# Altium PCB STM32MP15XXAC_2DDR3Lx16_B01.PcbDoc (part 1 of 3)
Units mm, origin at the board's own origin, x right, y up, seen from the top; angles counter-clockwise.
Board outline 89 x 120 mm, 4 copper layers (Top Layer, Signal Layer 1, Signal Layer 2, Bottom Layer), stack 1.571 mm thick; 152 components, 117 nets, 1047 pads, 460 vias.
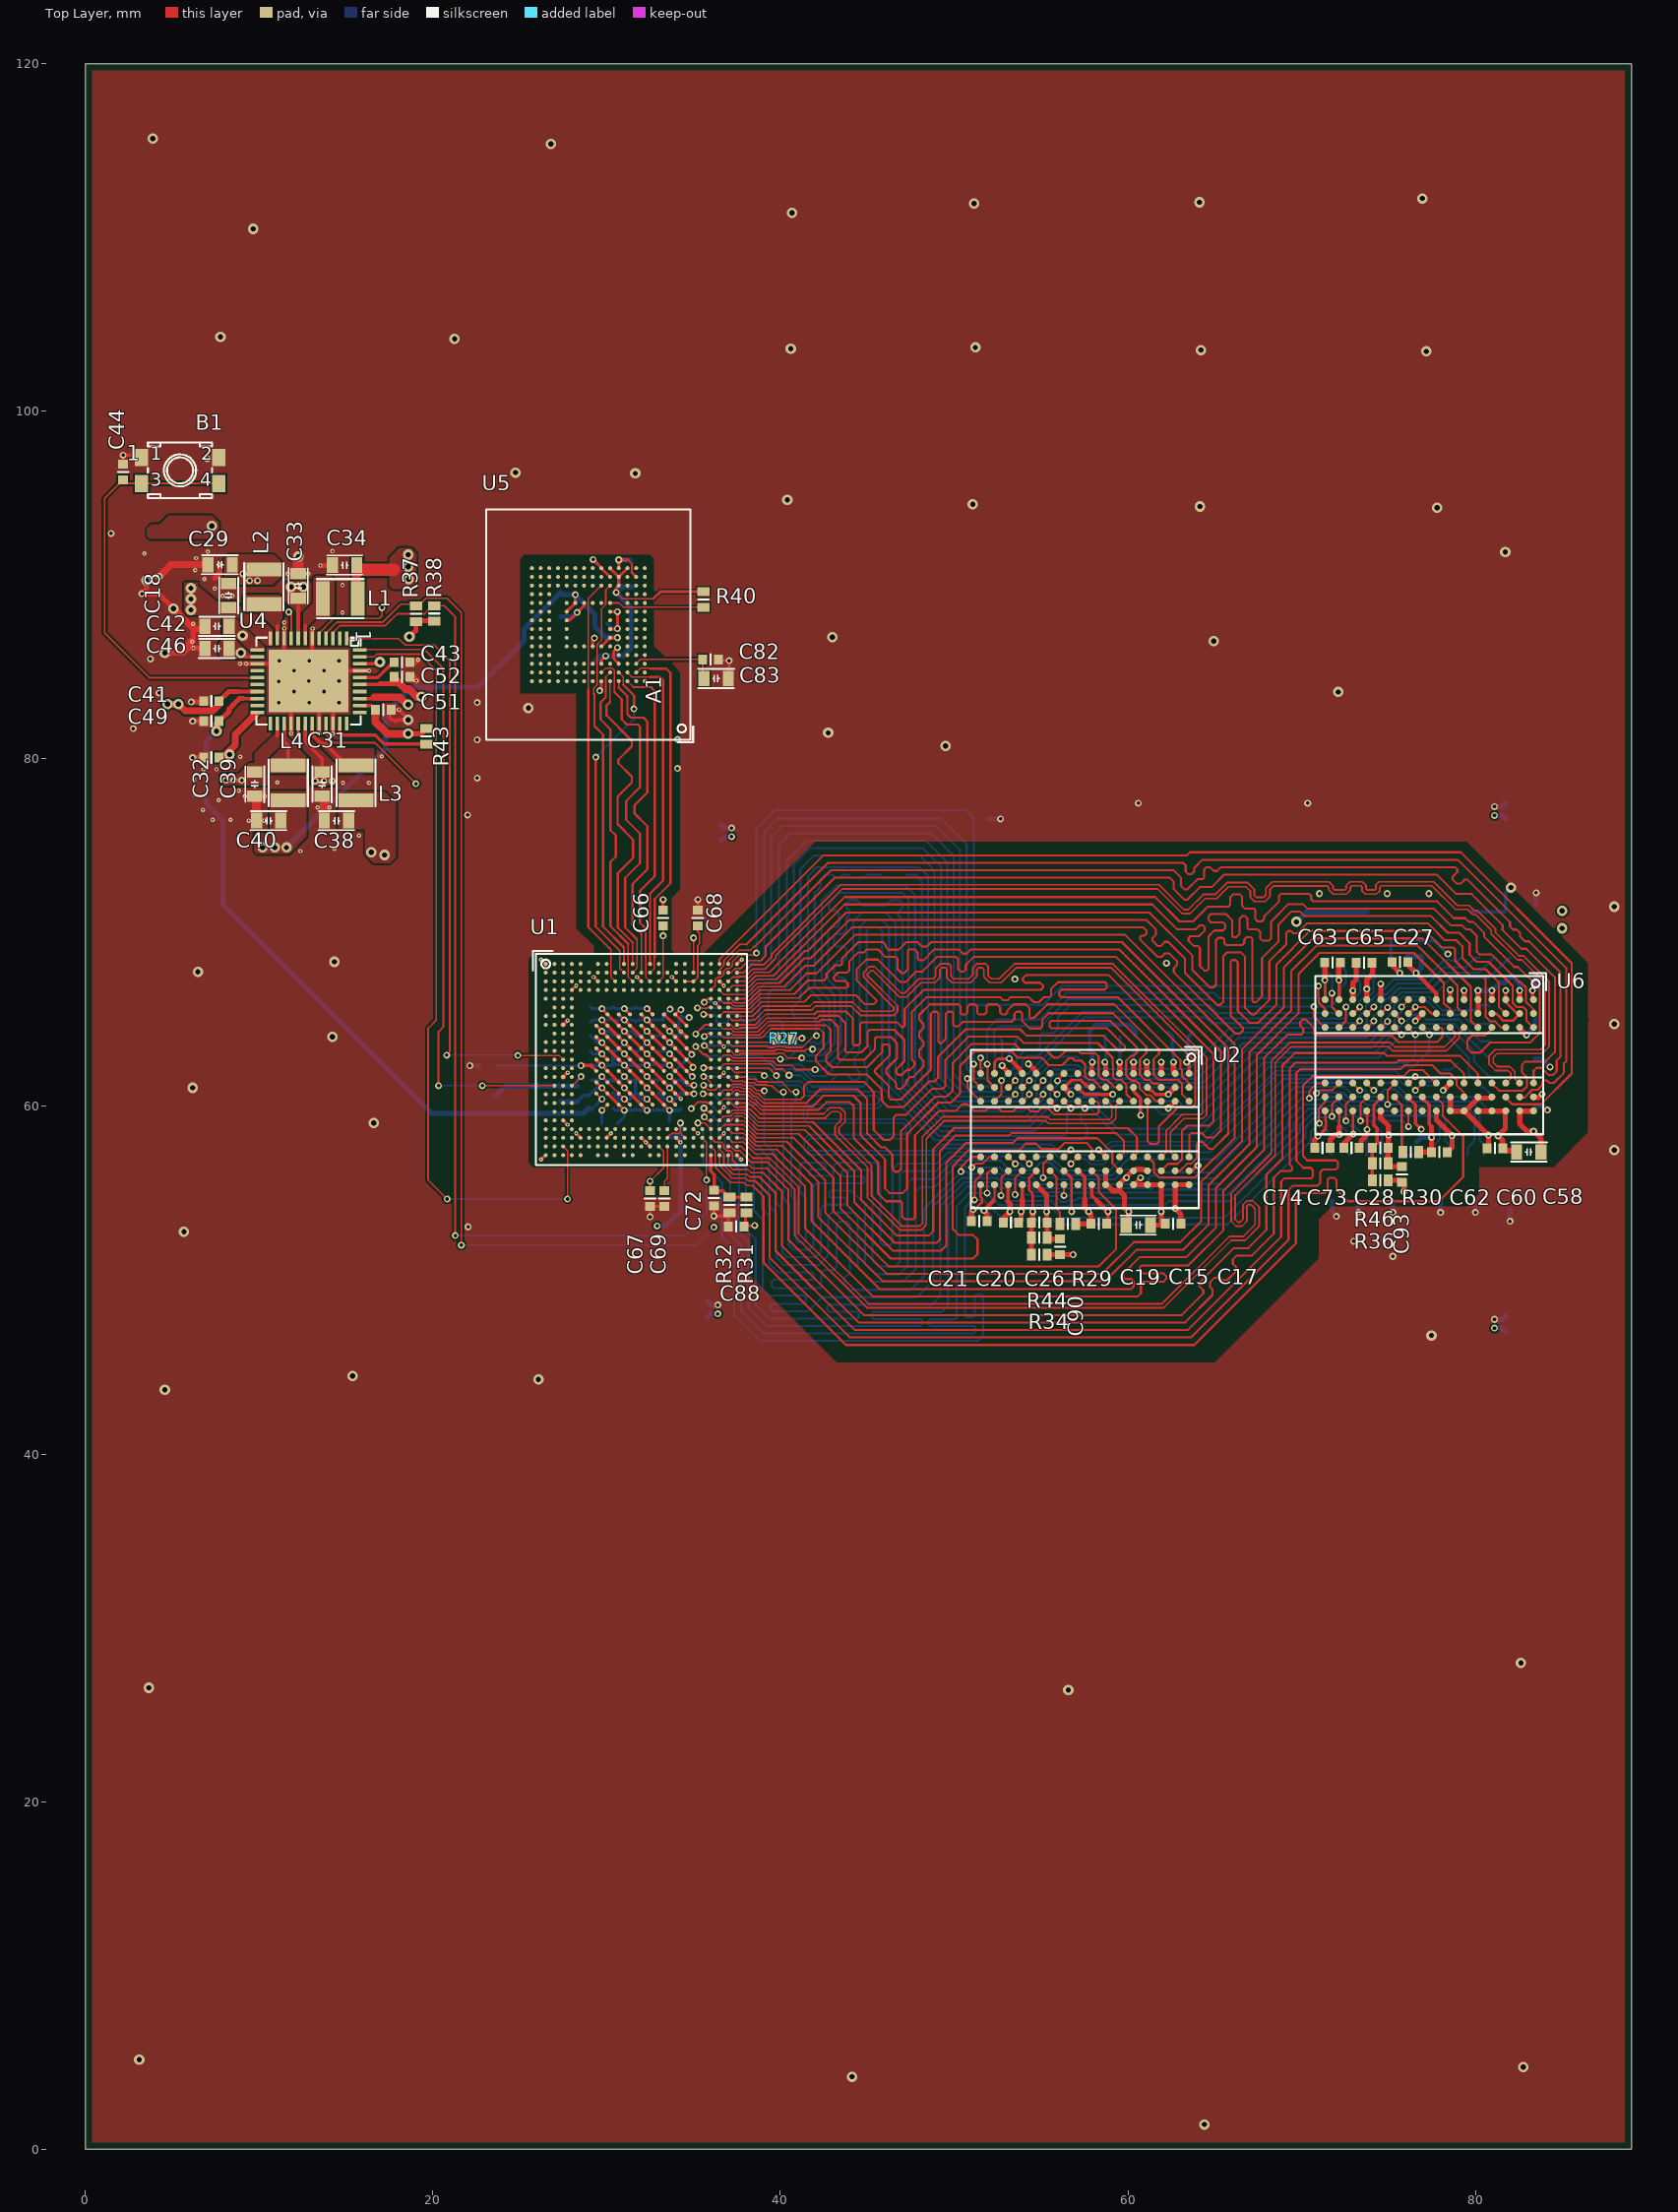
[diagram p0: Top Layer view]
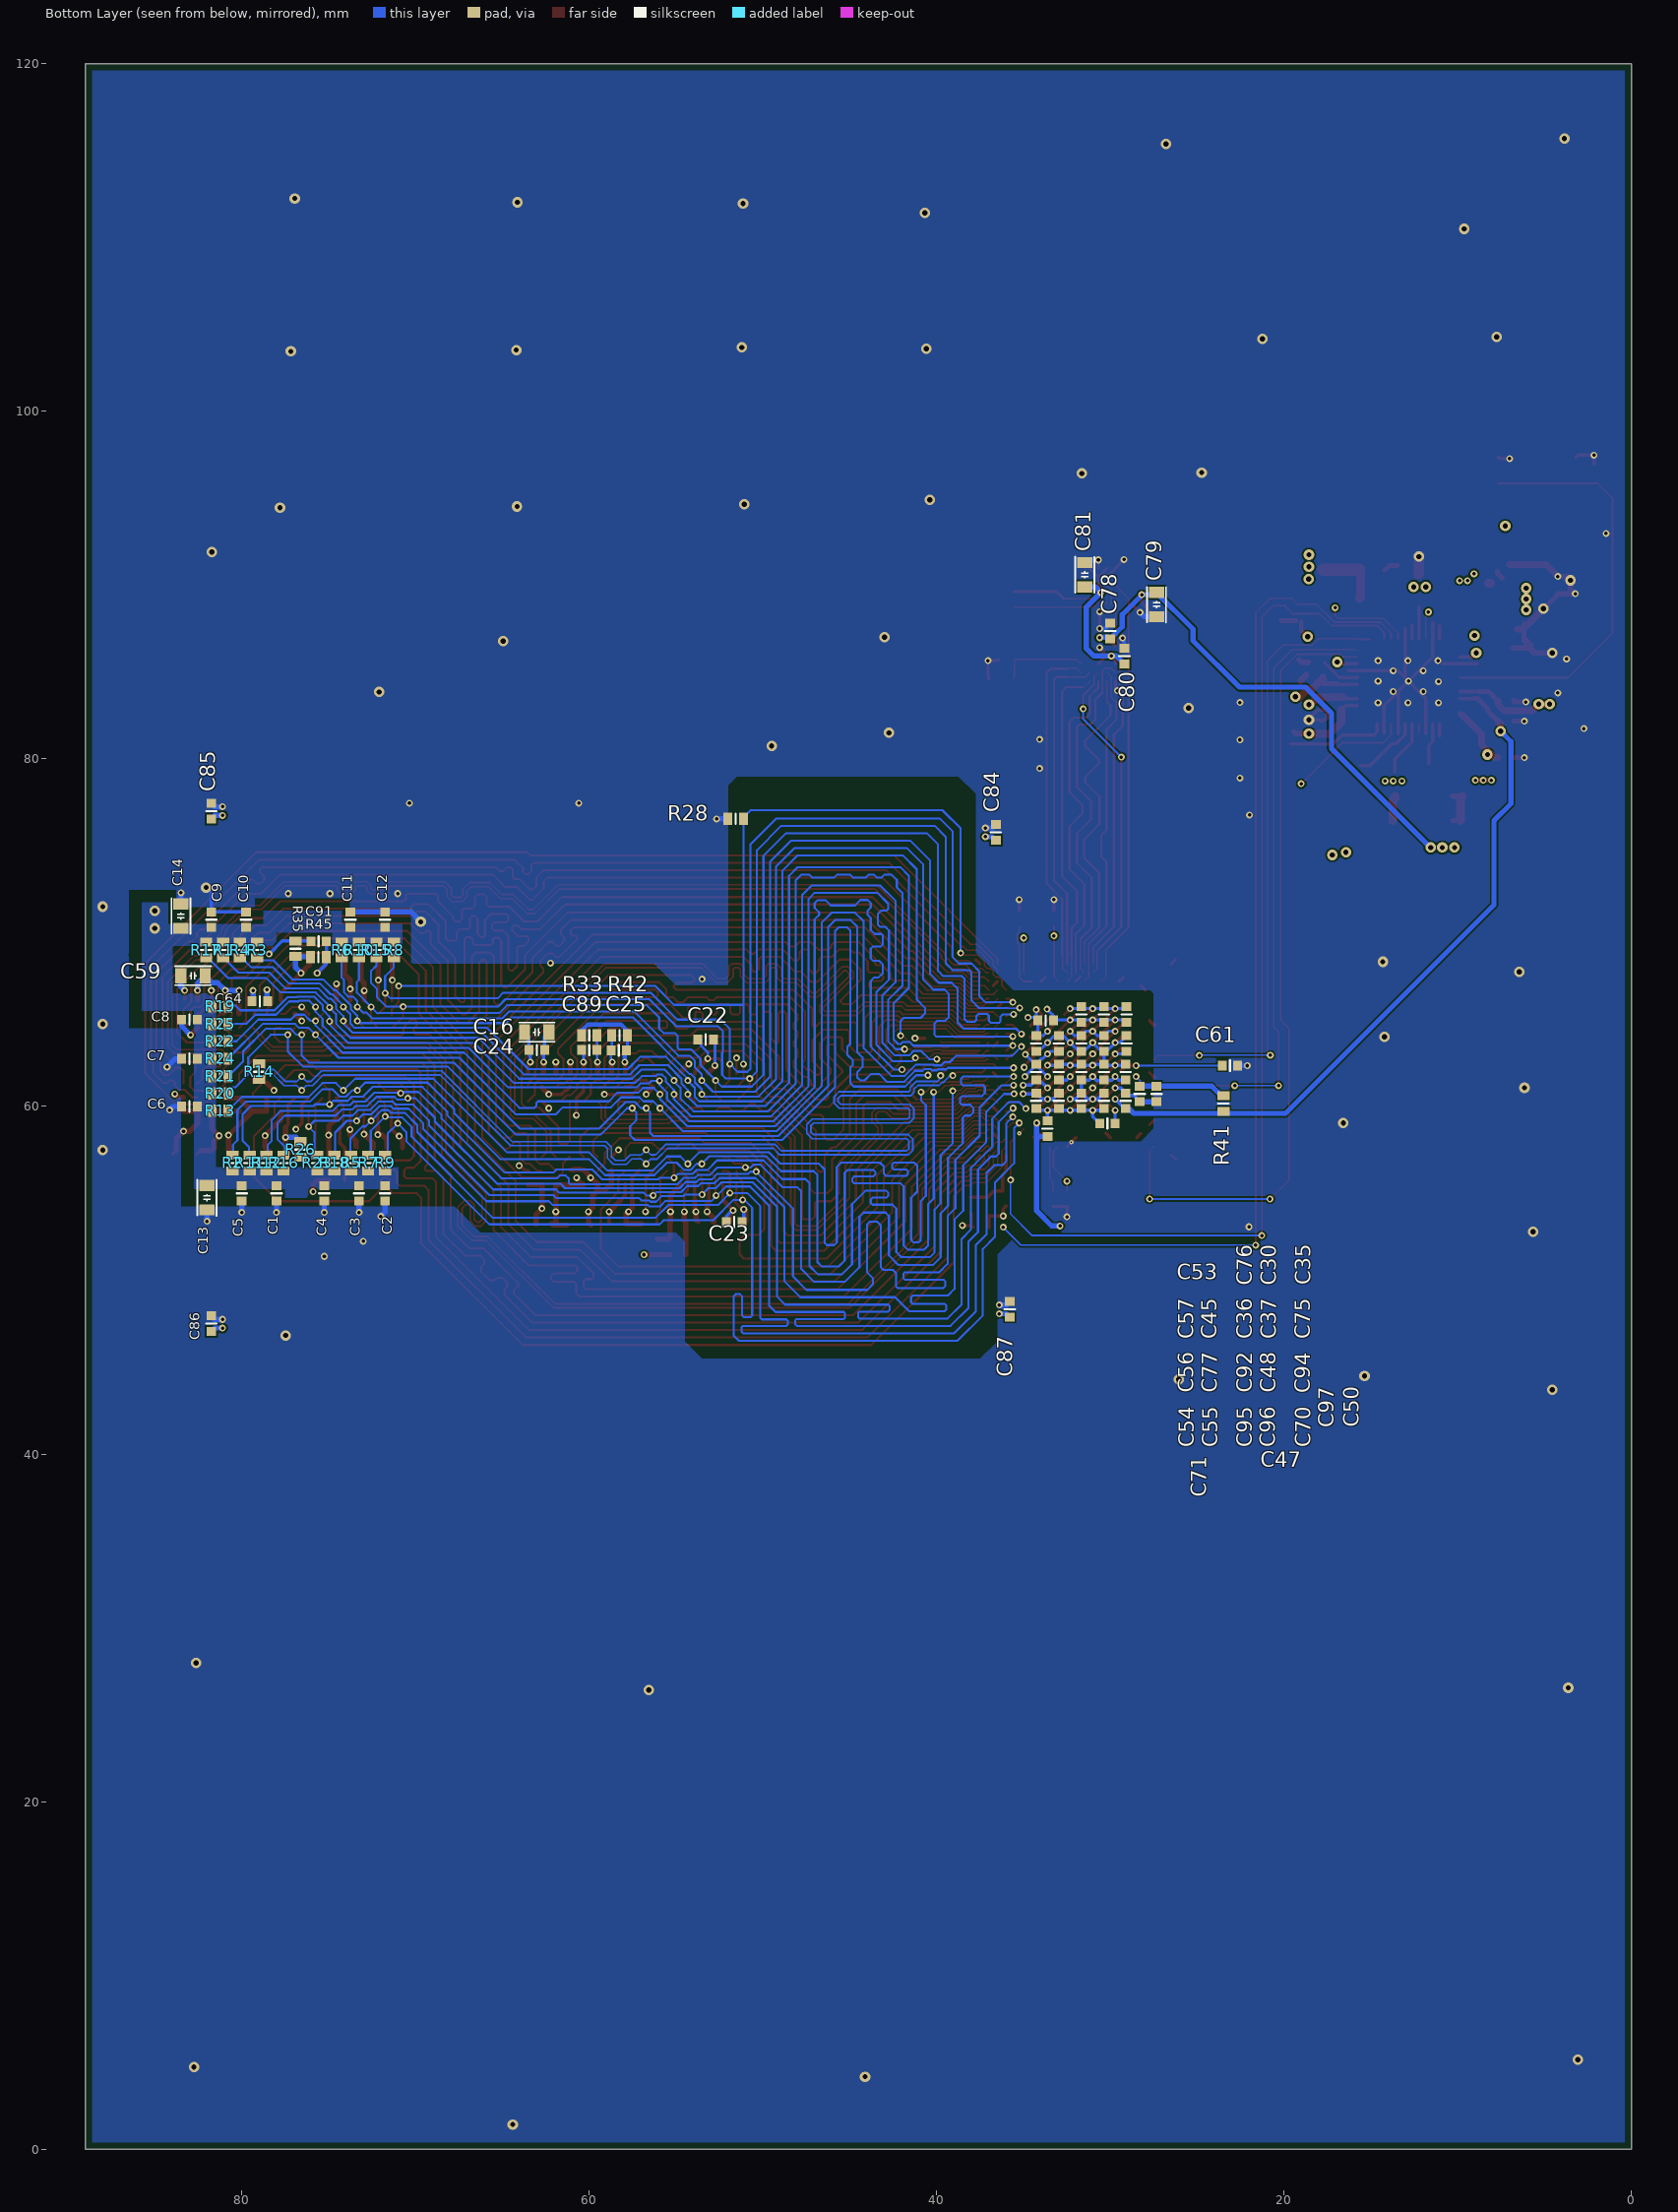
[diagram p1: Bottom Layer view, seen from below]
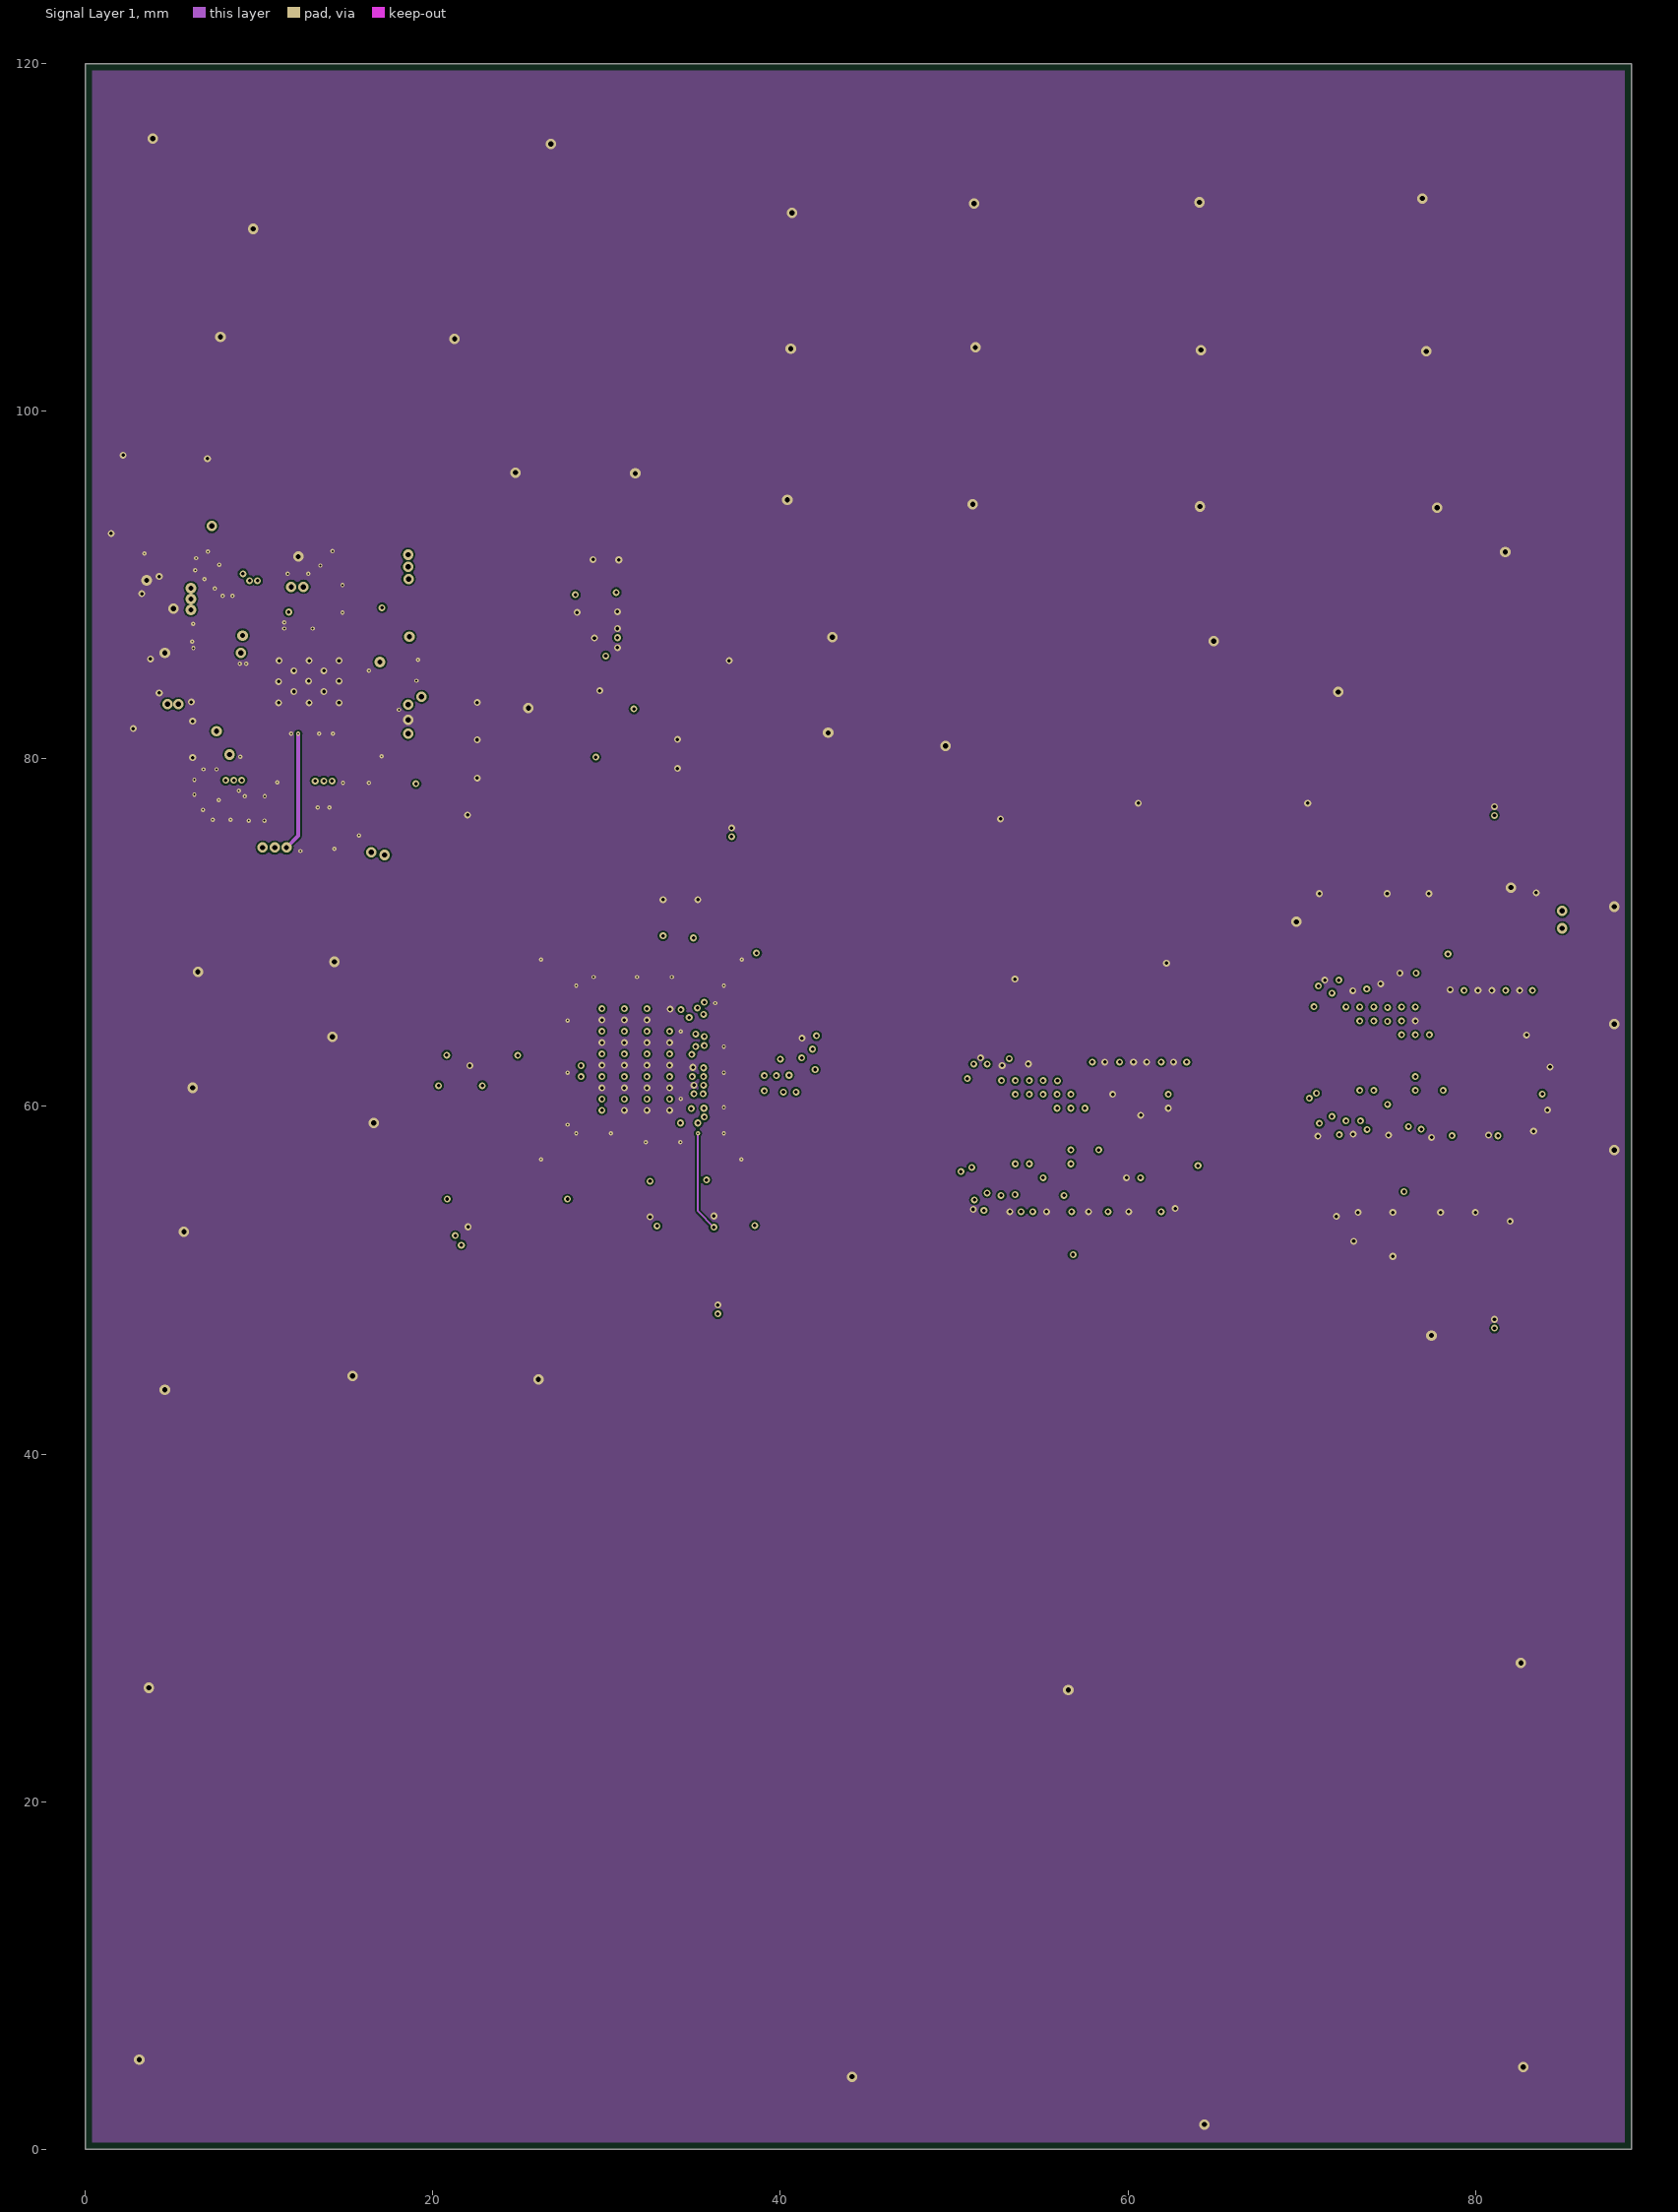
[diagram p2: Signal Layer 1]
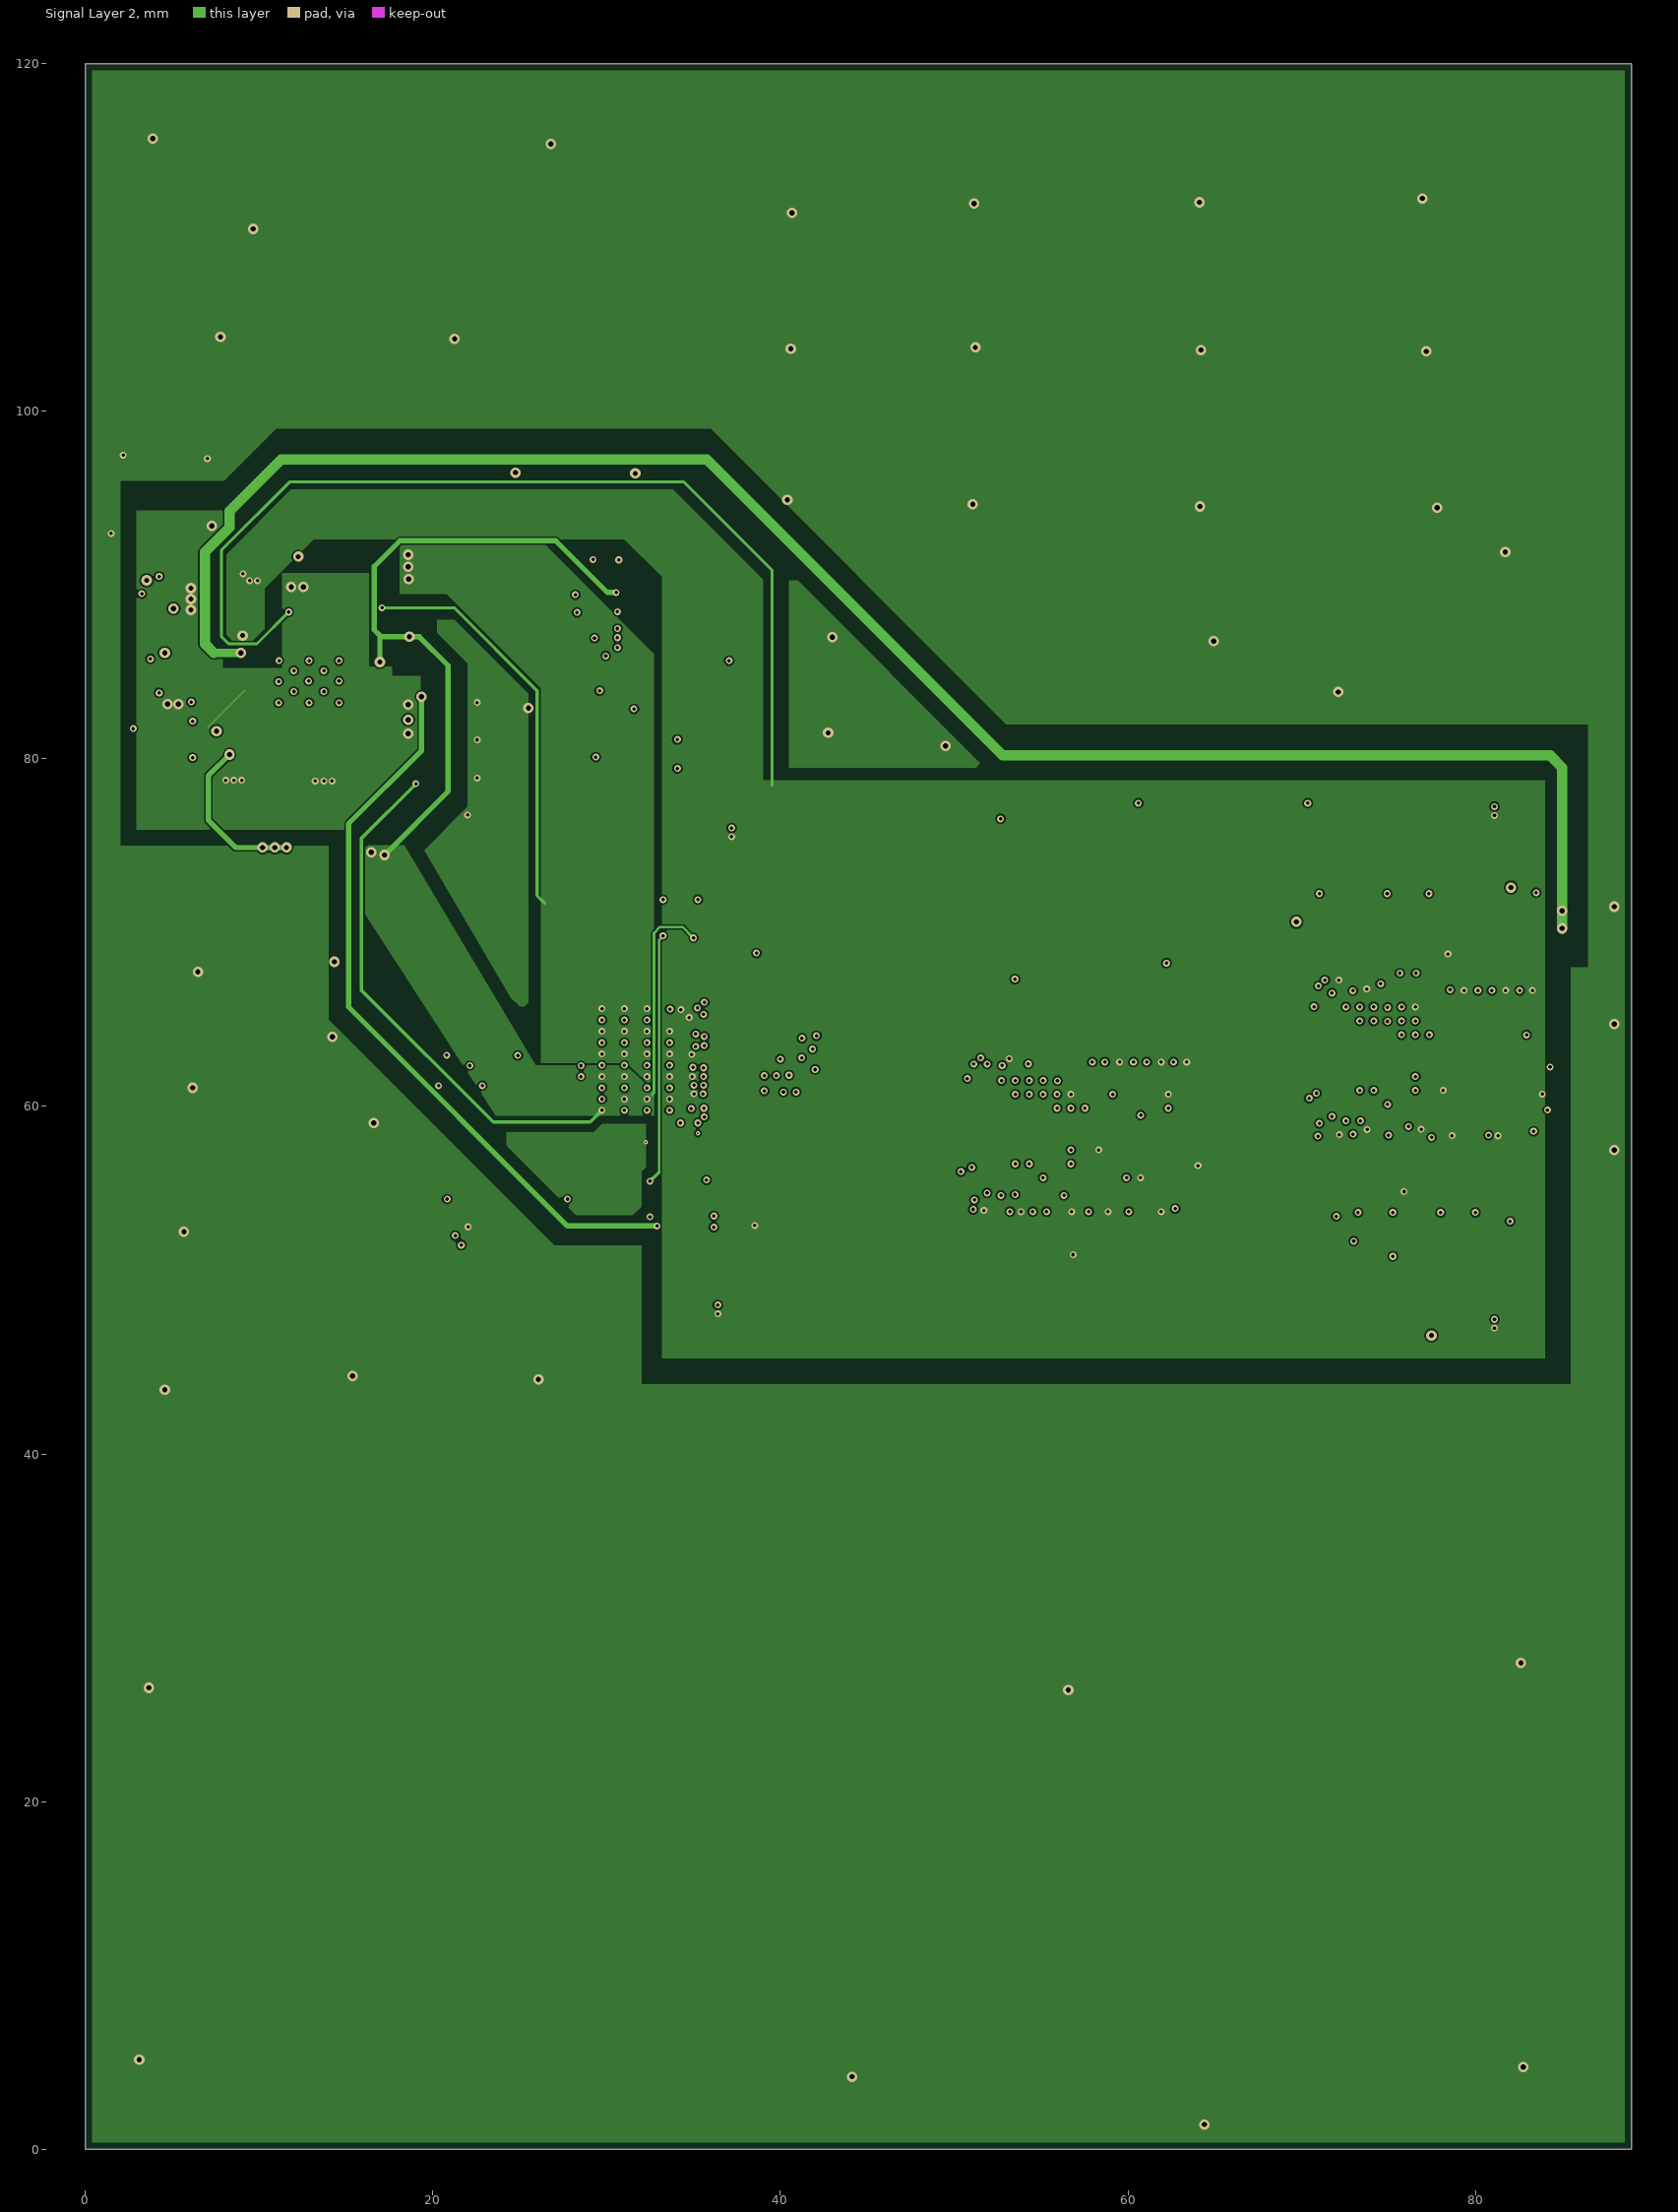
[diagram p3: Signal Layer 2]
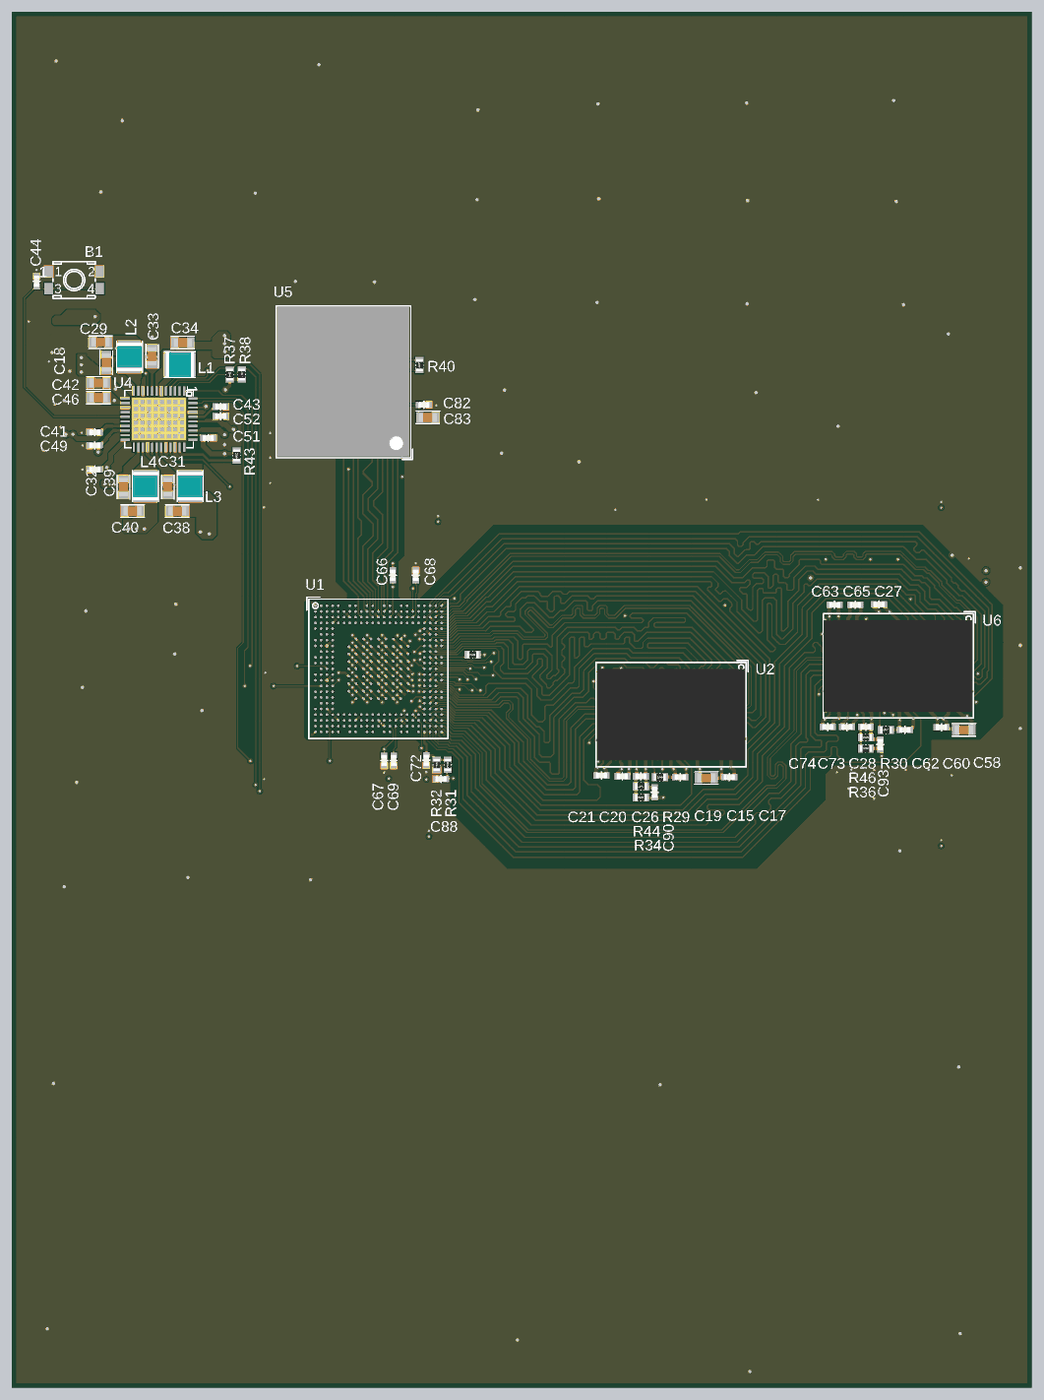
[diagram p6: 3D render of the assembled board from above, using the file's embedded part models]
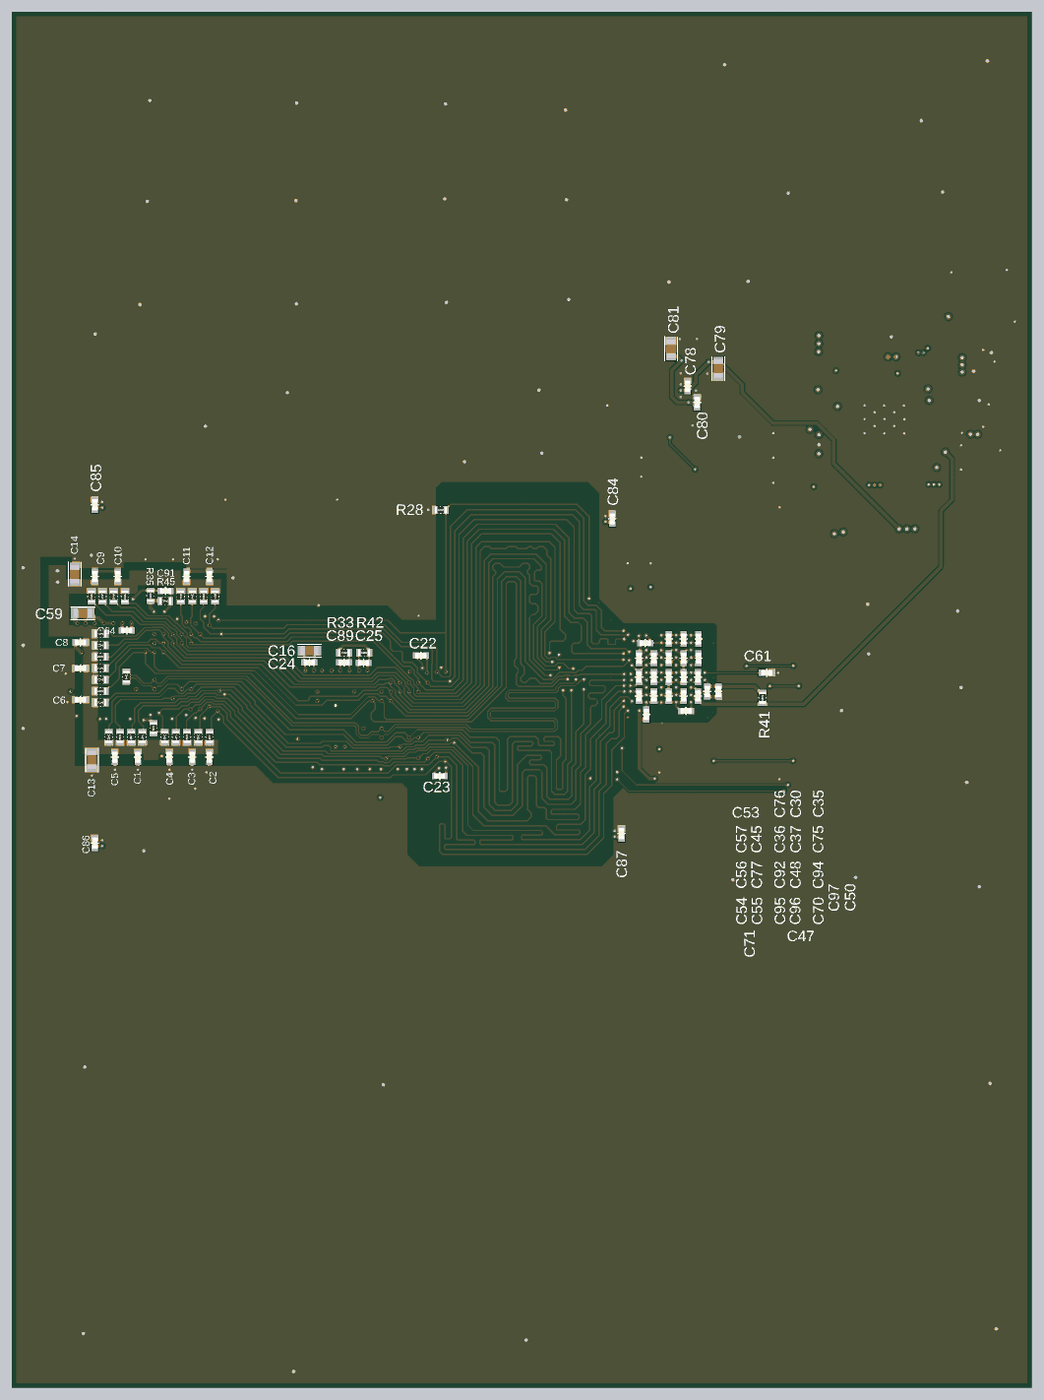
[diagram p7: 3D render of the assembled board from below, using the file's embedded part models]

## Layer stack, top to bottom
Top Solder: solder mask 0.0203, Solder Resist, Dk 3.5
Top Layer: signal copper 0.037
Dielectric 1: core 0.0986, FR-4, Dk 4.1
Signal Layer 1: signal copper 0.035
Dielectric 2: prepreg 1.23, Dk 4.25
Signal Layer 2: signal copper 0.035
Dielectric 3: core 0.0986, Dk 4.1
Bottom Layer: signal copper 0.037
Bottom Solder: solder mask 0.0203, Solder Resist, Dk 3.5

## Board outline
89,120 89,0 0,0 0,120

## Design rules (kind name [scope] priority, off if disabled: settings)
BoardOutlineClearance [All] p1: gap=0.4 ignorepadtopadclearanceinfootprint=FALSE
Clearance diff [InNetClass('diff')] p1: gap=0.1 ignorepadtopadclearanceinfootprint=FALSE except(0: Arc-Hole Track-Hole SMDPad-Hole THPad-Hole Via-Hole Fill-Hole Poly-Hole Region-Hole Text-Hole; 0.08: Track-SMDPad; 0.13: Track-Track; 0.15: Arc-Fill Track-Fill SMDPad-Fill THPad-Fill Via-Fill Fill-Fill; 0.2: Arc-THPad SMDPad-SMDPad SMDPad-THPad THPad-THPad)
Clearance [InNetClass('All Nets')] p2: gap=0.1 ignorepadtopadclearanceinfootprint=FALSE except(0: Arc-Hole Track-Hole SMDPad-Hole THPad-Hole Via-Hole Fill-Hole Poly-Hole Region-Hole Text-Hole; 0.08: Track-Track Track-SMDPad; 0.15: Arc-Fill Track-Fill SMDPad-Fill THPad-Fill Via-Fill Fill-Fill)
ComponentClearance [All] p1 off: gap=0.025 collisioncheckmode=3 verticalgap=2540 showdistances=TRUE
DiffPairsRouting [All] p1: maxlimit=0.13 minlimit=0.13 mostfreqgap=0.13 toplayer_minwidth=0.09 toplayer_maxwidth=0.13 toplayer_prefwidth=0.1 midlayer1_minwidth=0.09 midlayer1_maxwidth=0.13 midlayer1_prefwidth=0.1 midlayer2_minwidth=0.09 midlayer2_maxwidth=0.13 midlayer2_prefwidth=0.1 bottomlayer_minwidth=0.09 bottomlayer_maxwidth=0.13 bottomlayer_prefwidth=0.1 maxuncoupledlength=0.5
FanoutControl Fanout_BGA [IsBGA] p1: bgadir=Out bgaviamode=Closest fanoutstyle=Auto fanoutdirection=Alternating viagrid=0.025 // Fanout_BGA (Default Rule)
FanoutControl Fanout_LCC [IsLCC] p2: bgadir=Out bgaviamode=Closest fanoutstyle=Auto fanoutdirection=Alternating viagrid=0.025 // Fanout_LCC (Default Rule)
FanoutControl Fanout_SOIC [IsSOIC] p3: bgadir=Out bgaviamode=Closest fanoutstyle=Auto fanoutdirection=Alternating viagrid=0.025 // Fanout_SOIC (Default Rule)
FanoutControl Fanout_Small [(CompPinCount < 5)] p4: bgadir=Out bgaviamode=Closest fanoutstyle=Auto fanoutdirection=OutThenIn viagrid=0.025 // Fanout_Small (Default Rule)
FanoutControl Fanout_Default [All] p5: bgadir=Out bgaviamode=Closest fanoutstyle=Auto fanoutdirection=Alternating viagrid=0.025 // Fanout_Default (Default Rule)
Height [All] p1 off: minheight=0 maxheight=100 prefheight=0.5
HoleSize [All] p1: absolutevalues=TRUE maxlimit=10 minlimit=0.15 maxpercent=80.000 minpercent=20.000
HoleToHoleClearance [All] p1: gap=0.25 allowstackedmicrovias=TRUE
Length Length_SDMMC1 [InNetClass('NETC_SDMMC1')] p1: maxlimit=86 minlimit=81
MatchedLengths [All] p1: tolerance=25.4 checknetsindiffpair=FALSE checkdiffpairvsdiffpair=TRUE checkxsignals=TRUE checkothers=TRUE
MinimumSolderMaskSliver [All] p1: minsoldermaskwidth=0
PlaneClearance [All] p1: clearance=0.6
PlaneConnect [All] p1: planeconnectstyle=Direct reliefexpansion=0.508 reliefentries=4 reliefconductorwidth=0.254 reliefairgap=0.254
PolygonConnect PolygonConnect_notr [All vs (IsNamedPolygon('NO TR'))] p1: connectstyle=Direct reliefconductorwidth=0.254 reliefentries=4 polygonreliefangle="90 Angle" airgapwidth=0.254
PolygonConnect PolygonConnect_VTT_DDR [All vs IsNamedPolygon('VTT_DDR_BOT')] p2: connectstyle=Direct reliefconductorwidth=0.254 reliefentries=4 polygonreliefangle="45 Angle" airgapwidth=0.254
PolygonConnect [All] p3: connectstyle=Direct reliefconductorwidth=0.254 reliefentries=4 polygonreliefangle="45 Angle" airgapwidth=0.254
RoomDefinition U_2DDR3L_16bits [InComponentClass('U_2DDR3L_16bits')] p1 off: confinementstyle=ConfineIn formatcopy=TRUE lockcomponents=FALSE outline 87.147,1.416 97.048,1.416 97.048,16.991 87.147,16.991
RoomDefinition U_STM32_MPU_IOs [InComponentClass('U_STM32_MPU_IOs')] p2 off: confinementstyle=ConfineIn formatcopy=TRUE lockcomponents=FALSE outline 88.575,2.075 139.375,2.075 139.375,27.475 88.575,27.475
RoomDefinition U_Power_MPU [InComponentClass('U_Power_MPU')] p3 off: confinementstyle=ConfineIn formatcopy=TRUE lockcomponents=FALSE outline 87.122,16.916 100.898,16.916 100.898,22.892 87.122,22.892
RoomDefinition U_eMMC [InComponentClass('U_eMMC')] p4 off: confinementstyle=ConfineIn formatcopy=TRUE lockcomponents=FALSE outline 87.122,1.416 129.449,1.416 129.449,15.666 87.122,15.666
RoomDefinition U_Power_PMIC [InComponentClass('U_Power_PMIC')] p5 off: confinementstyle=ConfineIn formatcopy=TRUE lockcomponents=FALSE outline 87.122,8.666 203.578,8.666 203.578,17.666 87.122,17.666
RoutingVias RoutingVias_GND [InNetClass('GND')] p1: holewidth=0.3 width=0.6 viastyle="Through Hole" minholewidth=0.2 minwidth=0.4 maxholewidth=0.3 maxwidth=0.6
RoutingVias RoutingVias_ALIMS [InNetClass('ALIMS')] p2: holewidth=0.3 width=0.6 viastyle="Through Hole" minholewidth=0.2 minwidth=0.4 maxholewidth=0.3 maxwidth=0.6
RoutingVias [All] p3: holewidth=0.2 width=0.4 viastyle="Through Hole" minholewidth=0.2 minwidth=0.4 maxholewidth=0.3 maxwidth=0.6
SilkToSilkClearance [All] p1: silktosilkclearance=0
SilkToSolderMaskClearance [IsPad] p1: minsilkscreentomaskgap=0 clearancetoexposedcopper=TRUE
SolderMaskExpansion [All] p1: expansion=0.05 istentingtop=FALSE
Width VDD_DDR [InNet('VDD_DDR')] p1: maxlimit=1.5 minlimit=0.1 preferedwidth=0.3 minimp=50.000000 maximp=50.000000 favimp=50.000000
Width Width_VCORE [InNet('VDD_CORE')] p2: maxlimit=0.2 minlimit=0.175 preferedwidth=0.2
Width Width_gnd [InNet('GND')] p3: maxlimit=0.3 minlimit=0.1 preferedwidth=0.15
Width [All] p4: maxlimit=1 minlimit=0.09 preferedwidth=0.12 minimp=50.000000 maximp=50.000000 favimp=50.000000
15 further rules are at their usual default settings.

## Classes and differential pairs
net class eMMC_SDIO2_D[0..7]: eMMC_SDIO2_D0 eMMC_SDIO2_D1 eMMC_SDIO2_D2 eMMC_SDIO2_D3 eMMC_SDIO2_D4 eMMC_SDIO2_D5 eMMC_SDIO2_D6 eMMC_SDIO2_D7
component class U_STM32_MPU_IOs: C72 C88 R27 R31 R32 R37 R38 U1
component class U_eMMC: C78 C79 C80 C81 C82 C83 R40 U5
component class U_Power_PMIC: B1 C18 C29 C31 C32 C33 C34 C38 C39 C40 C41 C42 C43 C44 C46 C49 C51 C52 L1 L2 L3 L4 R43 U4
component class U_Power_MPU: C30 C35 C36 C37 C45 C47 C48 C50 C53 C54 C55 C56 C57 C61 C66 C67 C68 C69 C70 C71 C75 C76 C77 C92 C94 C95 C96 C97 R41
component class U_2DDR3L_16bits: C1 C2 C3 C4 C5 C6 C7 C8 C9 C10 C11 C12 C13 C14 C15 C16 C17 C19 C20 C21 C22 C23 C24 C25 C26 C27 C28 C58 C59 C60 C62 C63 C64 C65 C73 C74 C84 C85 C86 C87 C89 C90 C91 C93 R1 R2 R3 R4 R5 R6 R7 R8 R9 R10 R11 R12 R13 R14 R15 R16 R17 R18 R19 R20 R21 R22 R23 R24 R25 R26 R28 R29 R30 R33 R34 R35 R36 R42 R44 R45 R46 U2 U6
polygon class POLY_DIRECT_ALL: NETC906_2_L01_P192
differential pair class DIFF_DQS0: DDR_DQS0
differential pair class DIFF_DQS1: DDR_DQS1
differential pair class DIFF_CLK: DDR_CLK
differential pair DDR_DQS1: +DDR_DQS1_P -DDR_DQS1_N
differential pair DDR_DQS0: +DDR_DQS0_P -DDR_DQS0_N
differential pair DDR_CLK: +DDR_CLK_P -DDR_CLK_N
differential pair DDR_DQS2: +DDR_DQS2_P -DDR_DQS2_N
differential pair DDR_DQS3: +DDR_DQS3_P -DDR_DQS3_N

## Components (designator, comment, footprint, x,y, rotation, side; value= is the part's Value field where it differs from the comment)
B1 "SW-PUSH-TS-02H-Blue" SWI_JIUBABA_C-TS-02H-2-5-B-V-T_R_BLUE 5.45,96.6 r0 top
C1 "Capacitor" C0402 78,55 r270 bottom value=100nF
C2 "Capacitor" C0402 71.75,55 r270 bottom value=100nF
C3 "Capacitor" C0402 73.25,55 r270 bottom value=100nF
C4 "Capacitor" C0402 75.25,55 r270 bottom value=100nF
C5 "Capacitor" C0402 80,55 r270 bottom value=100nF
C6 "Capacitor" C0402 83,60 r0 bottom value=100nF
C7 "Capacitor" C0402 83,62.75 r0 bottom value=100nF
C8 "Capacitor" C0402 83,65 r0 bottom value=100nF
C9 "Capacitor" C0402 81.75,70.75 r90 bottom value=100nF
C10 "Capacitor" C0402 79.75,70.75 r90 bottom value=100nF
C11 "Capacitor" C0402 73.75,70.75 r90 bottom value=100nF
C12 "Capacitor" C0402 71.75,70.75 r90 bottom value=100nF
C13 "Capacitor" C0603 82,54.75 r90 bottom value=22uF
C14 "Capacitor" C0603 83.5,70.95 r270 bottom value=22uF
C15 "Capacitor" C0603 60.6,53.175 r0 top value=10uF
C16 "Capacitor" C0603 63.025,64.275 r0 bottom value=10uF
C17 "Capacitor" C0402 62.6,53.25 r0 top value=100nF
C18 "Capacitor" C0603 8.25,89.4 r270 top value=10uF
C19 "Capacitor" C0402 58.325,53.25 r180 top value=100nF
C20 "Capacitor" C0402 53.275,53.325 r180 top value=100nF
C21 "Capacitor" C0402 51.45,53.4 r180 top value=100nF
C22 "Capacitor" C0402 53.3,63.85 r180 bottom value=100nF
C23 "Capacitor" C0402 51.65,53.35 r180 bottom value=100nF
C24 "Capacitor" C0402 63.025,63.25 r180 bottom value=100nF
C25 "Capacitor" C0402 58.3,63.225 r0 bottom value=100nF
C26 "Capacitor" C0402 54.9,53.325 r0 top value=100nF
C27 "Capacitor" C0402 75.67,68.315 r180 top value=100nF
C28 "Capacitor" C0402 74.525,57.625 r0 top value=100nF
C29 "Capacitor" C0603 7.75,91.175 r0 top value=22uF
C30 "Capacitor" C0402 30.375,65.3 r90 bottom value=1uF
C31 "Capacitor" C0603 13.625,78.55 r90 top value=10uF
C32 "Capacitor" C0402 7.25,80.075 r0 top value=1uF
C33 "Capacitor" C0603 12.25,89.95 r270 top value=10uF
C34 "Capacitor" C0603 14.925,91.15 r0 top value=22uF
C35 "Capacitor" C0402 29.075,65.3 r90 bottom value=1uF
C36 "Capacitor" C0402 31.675,63.625 r90 bottom value=1uF
C37 "Capacitor" C0402 30.375,63.625 r90 bottom value=1uF
C38 "Capacitor" C0603 14.45,76.45 r0 top value=22uF
C39 "Capacitor" C0603 9.75,78.55 r90 top value=10uF
C40 "Capacitor" C0603 10.55,76.45 r0 top value=22uF
C41 "Capacitor" C0402 7.25,83.325 r0 top value=1uF
C42 "Capacitor" C0603 7.575,87.625 r0 top value=10uF
C43 "Capacitor" C0402 18.234,85.562 r0 top value=4.7uF
C44 "Capacitor" C0402 2.175,96.5 r270 top value=10nF
C45 "Capacitor" C0402 32.975,63.625 r270 bottom value=1uF
C46 "Capacitor" C0603 7.575,86.35 r0 top value=10uF
C47 "Capacitor" C0402 30.175,59.025 r180 bottom value=1uF
C48 "Capacitor" C0402 30.375,61.975 r270 bottom value=1uF
C49 "Capacitor" C0402 7.25,82.175 r0 top value=4.7uF
C50 "Capacitor" C0402 27.35,60.725 r90 bottom value=1uF
C51 "Capacitor" C0402 17.15,82.825 r180 top value=4.7uF
C52 "Capacitor" C0402 18.225,84.725 r180 top value=4.7uF
C53 "Capacitor" C0402 33.725,64.95 r0 bottom value=1uF
C54 "Capacitor" C0402 34.275,60.325 r90 bottom value=1uF
C55 "Capacitor" C0402 32.975,60.325 r90 bottom value=1uF
C56 "Capacitor" C0402 34.275,61.975 r90 bottom value=1nF
C57 "Capacitor" C0402 34.275,63.625 r90 bottom value=1nF
C58 "Capacitor" C0603 83.075,57.375 r180 top value=10uF
C59 "Capacitor" C0603 82.8,67.525 r0 bottom value=10uF
C60 "Capacitor" C0402 81.125,57.6 r180 top value=100nF
C61 "Capacitor" C0402 23.125,62.35 r0 bottom value=100nF
C62 "Capacitor" C0402 77.925,57.375 r180 top value=100nF
C63 "Capacitor" C0402 71.79,68.285 r180 top value=100nF
C64 "Capacitor" C0402 78.95,66.05 r180 bottom value=100nF
C65 "Capacitor" C0402 73.59,68.275 r180 top value=100nF
C66 "Capacitor" C0402 33.25,70.85 r270 top value=100nF
C67 "Capacitor" C0402 32.5,54.7 r90 top value=2.2uF
C68 "Capacitor" C0402 35.25,70.85 r270 top value=2.2uF
C69 "Capacitor" C0402 33.325,54.7 r90 top value=2.2uF
C70 "Capacitor" C0402 29.125,60.325 r270 bottom value=1uF
C71 "Capacitor" C0402 33.625,58.725 r270 bottom value=100nF
C72 "Capacitor" C0402 36.175,54.725 r90 top value=100nF
C73 "Capacitor" C0402 72.875,57.625 r180 top value=100nF
C74 "Capacitor" C0402 71.2,57.625 r180 top value=100nF
C75 "Capacitor" C0402 29.075,63.625 r270 bottom value=1uF
C76 "Capacitor" C0402 31.675,65.3 r90 bottom value=1uF
C77 "Capacitor" C0402 32.975,61.975 r270 bottom value=1uF
C78 "Capacitor" C0402 30.025,87.35 r270 bottom value=100nF
C79 "Capacitor" C0603 27.35,88.875 r90 bottom value=2.2uF
C80 "Capacitor" C0402 29.2,85.925 r270 bottom value=100nF
C81 "Capacitor" C0603 31.475,90.6 r270 bottom value=2.2uF
C82 "Capacitor" C0402 35.975,85.725 r180 top value=100nF
C83 "Capacitor" C0603 36.3,84.625 r180 top value=2.2uF
C84 "Capacitor" C0402 36.6,75.775 r90 bottom value=100nF
C85 "Capacitor" C0402 81.75,77 r90 bottom value=100nF
C86 "Capacitor" C0402 81.75,47.5 r90 bottom value=100nF
C87 "Capacitor" C0402 35.8,48.325 r90 bottom value=100nF
C88 "Capacitor" C0402 37.45,53.1 r0 top value=100nF
C89 "Capacitor" C0402 60,63.25 r0 bottom value=100nF
C90 "Capacitor" C0402 56.1,51.925 r90 top value=100nF
C91 "Capacitor" C0402 75.575,69.5 r180 bottom value=100nF
C92 "Capacitor" C0402 31.675,61.975 r270 bottom value=1uF
C93 "Capacitor" C0402 75.775,56.1 r90 top value=100nF
C94 "Capacitor" C0402 29.125,61.975 r270 bottom value=1uF
C95 "Capacitor" C0402 31.675,60.325 r90 bottom value=1uF
C96 "Capacitor" C0402 30.375,60.325 r90 bottom value=1uF
C97 "Capacitor" C0402 28.325,60.725 r90 bottom value=10nF
L1 "IND_1uH_42mohm_3.2A" IND_2520_TOKO_DFE252012P 14.675,89.225 r0 top value=1uH
L2 "IND_1uH_42mohm_3.2A" IND_2520_TOKO_DFE252012P 10.275,89.9 r90 top value=1uH
L3 "IND_1uH_42mohm_3.2A" IND_2520_TOKO_DFE252012P 15.575,78.625 r270 top value=1uH
L4 "IND_1uH_42mohm_3.2A" IND_2520_TOKO_DFE252012P 11.675,78.625 r270 top value=1uH
R1 "Resistor" R0402 81.075,69 r90 bottom value=56R
R2 "Resistor" R0402 80.525,56.75 r270 bottom value=56R
R3 "Resistor" R0402 79.125,69 r90 bottom value=56R
R4 "Resistor" R0402 80.1,69 r90 bottom value=56R
R5 "Resistor" R0402 73.7,56.75 r270 bottom value=56R
R6 "Resistor" R0402 74.25,69 r90 bottom value=56R
R7 "Resistor" R0402 72.725,56.75 r270 bottom value=56R
R8 "Resistor" R0402 71.25,69 r90 bottom value=56R
R9 "Resistor" R0402 71.75,56.75 r270 bottom value=56R
R10 "Resistor" R0402 73.25,69 r90 bottom value=56R
R11 "Resistor" R0402 79.55,56.75 r270 bottom value=56R
R12 "Resistor" R0402 78.575,56.75 r270 bottom value=56R
R13 "Resistor" R0402 81.25,59.75 r0 bottom value=56R
R14 "Resistor" R0402 79,62 r90 bottom value=100R
R15 "Resistor" R0402 72.25,69 r90 bottom value=56R
R16 "Resistor" R0402 77.6,56.75 r270 bottom value=56R
R17 "Resistor" R0402 82.05,69 r90 bottom value=56R
R18 "Resistor" R0402 74.675,56.75 r270 bottom value=56R
R19 "Resistor" R0402 81.25,65.75 r0 bottom value=56R
R20 "Resistor" R0402 81.25,60.75 r0 bottom value=56R
R21 "Resistor" R0402 81.25,61.75 r0 bottom value=56R
R22 "Resistor" R0402 81.25,63.75 r0 bottom value=56R
R23 "Resistor" R0402 75.65,56.75 r270 bottom value=56R
R24 "Resistor" R0402 81.25,62.75 r0 bottom value=56R
R25 "Resistor" R0402 81.25,64.75 r0 bottom value=56R
R26 "Resistor" R0402 76.625,57.525 r270 bottom value=10K
R27 "Resistor" R0402 40.225,63.925 r0 top value="240R 1%"
R28 "Resistor" R0402 51.575,76.55 r180 bottom value=10K
R29 "Resistor" R0402 56.55,53.25 r180 top value="240R 1%"
R30 "Resistor" R0402 76.275,57.375 r180 top value="240R 1%"
R31 "Resistor" R0402 38.05,54.325 r270 top value=1K
R32 "Resistor" R0402 37.075,54.325 r90 top value=1K
R33 "Resistor" R0402 60,64.1 r180 bottom value=1K
R34 "Resistor" R0402 54.9,51.475 r0 top value=1K
R35 "Resistor" R0402 76.9,69.075 r90 bottom value=1K
R36 "Resistor" R0402 74.525,55.75 r0 top value=1K
R37 "Resistor" R0402 19.025,88.35 r90 top value=1K5
R38 "Resistor" R0402 20.074,88.363 r90 top value=1K5
R40 "Resistor" R0402 35.575,89.175 r90 top value=10K
R41 "Resistor" R0402 23.5,60.175 r90 bottom value=0R
R42 "Resistor" R0402 58.25,64.1 r180 bottom value=1K
R43 "Resistor" R0402 19.625,81.3 r90 top value=47K
R44 "Resistor" R0402 54.9,52.45 r180 top value=1K
R45 "Resistor" R0402 75.6,68.6 r0 bottom value=1K
R46 "Resistor" R0402 74.525,56.725 r180 top value=1K
U1 "STM32MP157CAC3" ICC_TFBGA361_12X12_STM32MP157CAC3_P050-065 32,62.7 r0 top locked
U2 "NT5CC256M16ER-EK" ICC_VFBGA96_9X13_P080 57.525,58.7 r270 top locked
U4 "STPMU1" ICC_WFQFN44-EPAD_5X6_P040 12.85,84.475 r270 top value=STPMU1A
U5 "eMMC_THGBMDG5D1LBAIL" ICC_P-WFBGA153_13X11P5_P050 28.95,87.725 r90 top locked value=THGBMDG5D1LBAIL
U6 "NT5CC256M16ER-EK" ICC_VFBGA96_9X13_P080 77.35,62.95 r270 top locked

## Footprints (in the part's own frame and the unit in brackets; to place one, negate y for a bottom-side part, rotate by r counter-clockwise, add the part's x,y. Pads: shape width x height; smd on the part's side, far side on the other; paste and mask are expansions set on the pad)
C0402 [mm]
  rect 0.51x0.56 smd mask+0.05: 1(-0.45,0) 2(0.45,0)
  silkscreen extent 0,-0.3 0,0.3, body extent -0.5,-0.3 0.5,0.3, height 0.4
C0603 [mm]
  rect 0.64x0.89 smd mask+0.05: 1(-0.7,0) 2(0.7,0)
  silkscreen extent -1.05,-0.55 1.02,0.55, body extent -0.9,-0.5 0.9,0.5, height 1.4
ICC_P-WFBGA153_13X11P5_P050 [mm]
  round 0.23 smd mask+0.05: A1(-3.25,-3.25) A2(-3.25,-2.75) A3(-3.25,-2.25) A4(-3.25,-1.75) A5(-3.25,-1.25) A6(-3.25,-0.75) A7(-3.25,-0.25) A8(-3.25,0.25) A9(-3.25,0.75) A10(-3.25,1.25) A11(-3.25,1.75) A12(-3.25,2.25) A13(-3.25,2.75) A14(-3.25,3.25) B1(-2.75,-3.25) B2(-2.75,-2.75) B3(-2.75,-2.25) B4(-2.75,-1.75) B5(-2.75,-1.25) B6(-2.75,-0.75) B7(-2.75,-0.25) B8(-2.75,0.25) B9(-2.75,0.75) B10(-2.75,1.25) B11(-2.75,1.75) B12(-2.75,2.25) B13(-2.75,2.75) B14(-2.75,3.25) C1(-2.25,-3.25) C2(-2.25,-2.75) C3(-2.25,-2.25) C4(-2.25,-1.75) C5(-2.25,-1.25) C6(-2.25,-0.75) C7(-2.25,-0.25) C8(-2.25,0.25) C9(-2.25,0.75) C10(-2.25,1.25) C11(-2.25,1.75) C12(-2.25,2.25) C13(-2.25,2.75) C14(-2.25,3.25) D1(-1.75,-3.25) D2(-1.75,-2.75) D3(-1.75,-2.25) D4(-1.75,-1.75) D12(-1.75,2.25) D13(-1.75,2.75) D14(-1.75,3.25) E1(-1.25,-3.25) E2(-1.25,-2.75) E3(-1.25,-2.25) E5(-1.25,-1.25) E6(-1.25,-0.75) E7(-1.25,-0.25) E8(-1.25,0.25) E9(-1.25,0.75) E10(-1.25,1.25) E12(-1.25,2.25) E13(-1.25,2.75) E14(-1.25,3.25) F1(-0.75,-3.25) F2(-0.75,-2.75) F3(-0.75,-2.25) F5(-0.75,-1.25) F10(-0.75,1.25) F12(-0.75,2.25) F13(-0.75,2.75) F14(-0.75,3.25) G1(-0.25,-3.25) G2(-0.25,-2.75) G3(-0.25,-2.25) G5(-0.25,-1.25) G10(-0.25,1.25) G12(-0.25,2.25) G13(-0.25,2.75) G14(-0.25,3.25) H1(0.25,-3.25) H2(0.25,-2.75) H3(0.25,-2.25) H5(0.25,-1.25) H10(0.25,1.25) H12(0.25,2.25) H13(0.25,2.75) H14(0.25,3.25) J1(0.75,-3.25) J2(0.75,-2.75) J3(0.75,-2.25) J5(0.75,-1.25) J10(0.75,1.25) J12(0.75,2.25) J13(0.75,2.75) J14(0.75,3.25) K1(1.25,-3.25) K2(1.25,-2.75) K3(1.25,-2.25) K5(1.25,-1.25) K6(1.25,-0.75) K7(1.25,-0.25) K8(1.25,0.25) K9(1.25,0.75) K10(1.25,1.25) K12(1.25,2.25) K13(1.25,2.75) K14(1.25,3.25) L1(1.75,-3.25) L2(1.75,-2.75) L3(1.75,-2.25) L12(1.75,2.25) L13(1.75,2.75) L14(1.75,3.25) M1(2.25,-3.25) M2(2.25,-2.75) M3(2.25,-2.25) M4(2.25,-1.75) M5(2.25,-1.25) M6(2.25,-0.75) M7(2.25,-0.25) M8(2.25,0.25) M9(2.25,0.75) M10(2.25,1.25) M11(2.25,1.75) M12(2.25,2.25) M13(2.25,2.75) M14(2.25,3.25) N1(2.75,-3.25) N2(2.75,-2.75) N3(2.75,-2.25) N4(2.75,-1.75) N5(2.75,-1.25) N6(2.75,-0.75) N7(2.75,-0.25) N8(2.75,0.25) N9(2.75,0.75) N10(2.75,1.25) N11(2.75,1.75) N12(2.75,2.25) N13(2.75,2.75) N14(2.75,3.25) P1(3.25,-3.25) P2(3.25,-2.75) P3(3.25,-2.25) P4(3.25,-1.75) P5(3.25,-1.25) P6(3.25,-0.75) P7(3.25,-0.25) P8(3.25,0.25) P9(3.25,0.75) P10(3.25,1.25) P11(3.25,1.75) P12(3.25,2.25) P13(3.25,2.75) P14(3.25,3.25)
  silkscreen extent -6.78,-6.02 6.63,5.87, body extent -6.55,-5.8 6.55,5.8, height 1
ICC_TFBGA361_12X12_STM32MP157CAC3_P050-065 [mm] "IPC"
  round 0.23 smd mask+0.05: 1A2(-1.95,2.6) 1A3(-1.3,2.6) 1A4(-0.65,2.6) 1A5(0,2.6) 1A6(0.65,2.6) 1A7(1.3,2.6) 1A8(1.95,2.6) 1B1(-2.6,1.95) 1B2(-1.95,1.95) 1B3(-1.3,1.95) 1B4(-0.65,1.95) 1B5(0,1.95) 1B6(0.65,1.95) 1B7(1.3,1.95) 1B8(1.95,1.95) 1B9(2.6,1.95) 1C1(-2.6,1.3) 1C2(-1.95,1.3) 1C3(-1.3,1.3) 1C4(-0.65,1.3) 1C5(0,1.3) 1C6(0.65,1.3) 1C7(1.3,1.3) 1C8(1.95,1.3) 1C9(2.6,1.3) 1D1(-2.6,0.65) 1D2(-1.95,0.65) 1D3(-1.3,0.65) 1D4(-0.65,0.65) 1D5(0,0.65) 1D6(0.65,0.65) 1D7(1.3,0.65) 1D8(1.95,0.65) 1D9(2.6,0.65) 1E1(-2.6,0) 1E2(-1.95,0) 1E3(-1.3,0) 1E4(-0.65,0) 1E5(0,0) 1E6(0.65,0) 1E7(1.3,0) 1E8(1.95,0) 1E9(2.6,0) 1F1(-2.6,-0.65) 1F2(-1.95,-0.65) 1F3(-1.3,-0.65) 1F4(-0.65,-0.65) 1F5(0,-0.65) 1F6(0.65,-0.65) 1F7(1.3,-0.65) 1F8(1.95,-0.65) 1F9(2.6,-0.65) 1G1(-2.6,-1.3) 1G2(-1.95,-1.3) 1G3(-1.3,-1.3) 1G4(-0.65,-1.3) 1G5(0,-1.3) 1G6(0.65,-1.3) 1G7(1.3,-1.3) 1G8(1.95,-1.3) 1G9(2.6,-1.3) 1H1(-2.6,-1.95) 1H2(-1.95,-1.95) 1H3(-1.3,-1.95) 1H4(-0.65,-1.95) 1H5(0,-1.95) 1H6(0.65,-1.95) 1H7(1.3,-1.95) 1H8(1.95,-1.95) 1H9(2.6,-1.95) 1J2(-1.95,-2.6) 1J3(-1.3,-2.6) 1J4(-0.65,-2.6) 1J5(0,-2.6) 1J6(0.65,-2.6) 1J7(1.3,-2.6) 1J8(1.95,-2.6) A1(-5.5,5.5) A2(-5,5.5) A3(-4.5,5.5) A4(-4,5.5) A5(-3.5,5.5) A7(-2.5,5.5) A8(-2,5.5) A10(-1,5.5) A11(-0.5,5.5) A13(0.5,5.5) A14(1,5.5) A16(2,5.5) A17(2.5,5.5) A19(3.5,5.5) A20(4,5.5) A21(4.5,5.5) A22(5,5.5) A23(5.5,5.5) AA1(-5.5,-4.5) AA2(-5,-4.5) AA3(-4.5,-4.5) AA4(-4,-4.5) AA5(-3.5,-4.5) AA6(-3,-4.5) AA7(-2.5,-4.5) AA8(-2,-4.5) AA9(-1.5,-4.5) AA10(-1,-4.5) AA11(-0.5,-4.5) AA12(0,-4.5) AA13(0.5,-4.5) AA14(1,-4.5) AA15(1.5,-4.5) AA16(2,-4.5) AA17(2.5,-4.5) AA18(3,-4.5) AA19(3.5,-4.5) AA20(4,-4.5) AA21(4.5,-4.5) AA22(5,-4.5) AA23(5.5,-4.5) AB1(-5.5,-5) AB2(-5,-5) AB3(-4.5,-5) AB4(-4,-5) AB5(-3.5,-5) AB6(-3,-5) AB7(-2.5,-5) AB8(-2,-5) AB9(-1.5,-5) AB10(-1,-5) AB11(-0.5,-5) AB12(0,-5) AB13(0.5,-5) AB14(1,-5) AB15(1.5,-5) AB16(2,-5) AB17(2.5,-5) AB18(3,-5) AB19(3.5,-5) AB20(4,-5) AB21(4.5,-5) AB22(5,-5) AB23(5.5,-5) AC1(-5.5,-5.5) AC2(-5,-5.5) AC3(-4.5,-5.5) AC4(-4,-5.5) AC5(-3.5,-5.5) AC7(-2.5,-5.5) AC8(-2,-5.5) AC10(-1,-5.5) AC11(-0.5,-5.5) AC13(0.5,-5.5) AC14(1,-5.5) AC16(2,-5.5) AC17(2.5,-5.5) AC19(3.5,-5.5) AC20(4,-5.5) AC21(4.5,-5.5) AC22(5,-5.5) AC23(5.5,-5.5) B1(-5.5,5) B2(-5,5) B3(-4.5,5) B4(-4,5) B5(-3.5,5) B6(-3,5) B7(-2.5,5) B8(-2,5) B9(-1.5,5) B10(-1,5) B11(-0.5,5) B12(0,5) B13(0.5,5) B14(1,5) B15(1.5,5) B16(2,5) B17(2.5,5) B18(3,5) B19(3.5,5) B20(4,5) B21(4.5,5) B22(5,5) B23(5.5,5) C1(-5.5,4.5) C2(-5,4.5) C3(-4.5,4.5) C4(-4,4.5) C5(-3.5,4.5) C6(-3,4.5) C7(-2.5,4.5) C8(-2,4.5) C9(-1.5,4.5) C10(-1,4.5) C11(-0.5,4.5) C12(0,4.5) C13(0.5,4.5) C14(1,4.5) C15(1.5,4.5) C16(2,4.5) C17(2.5,4.5) C18(3,4.5) C19(3.5,4.5) C20(4,4.5) C21(4.5,4.5) C22(5,4.5) C23(5.5,4.5) D1(-5.5,4) D2(-5,4) D3(-4.5,4) D4(-4,4) D5(-3.5,4) D6(-3,4) D7(-2.5,4) D8(-2,4) D9(-1.5,4) D10(-1,4) D11(-0.5,4) D12(0,4) D13(0.5,4) D14(1,4) D15(1.5,4) D16(2,4) D17(2.5,4) D18(3,4) D19(3.5,4) D20(4,4) D21(4.5,4) D22(5,4) D23(5.5,4) E1(-5.5,3.5) E2(-5,3.5) E3(-4.5,3.5) E4(-4,3.5) E20(4,3.5) E21(4.5,3.5) E22(5,3.5) E23(5.5,3.5) F2(-5,3) F3(-4.5,3) F4(-4,3) F20(4,3) F21(4.5,3) F22(5,3) G1(-5.5,2.5) G2(-5,2.5) G3(-4.5,2.5) G4(-4,2.5) G20(4,2.5) G21(4.5,2.5) G22(5,2.5) G23(5.5,2.5) H1(-5.5,2) H2(-5,2) H3(-4.5,2) H4(-4,2) H20(4,2) H21(4.5,2) H22(5,2) H23(5.5,2) J2(-5,1.5) J3(-4.5,1.5) J4(-4,1.5) J20(4,1.5) J21(4.5,1.5) J22(5,1.5) K1(-5.5,1) K2(-5,1) K3(-4.5,1) K4(-4,1) K20(4,1) K21(4.5,1) K22(5,1) K23(5.5,1) L1(-5.5,0.5) L2(-5,0.5) L3(-4.5,0.5) L4(-4,0.5) L20(4,0.5) L21(4.5,0.5) L22(5,0.5) L23(5.5,0.5) M2(-5,0) M3(-4.5,0) M4(-4,0) M20(4,0) M21(4.5,0) M22(5,0) N1(-5.5,-0.5) N2(-5,-0.5) N3(-4.5,-0.5) N4(-4,-0.5) N20(4,-0.5) N21(4.5,-0.5) N22(5,-0.5) N23(5.5,-0.5) P1(-5.5,-1) P2(-5,-1) P3(-4.5,-1) P4(-4,-1) P20(4,-1) P21(4.5,-1) P22(5,-1) P23(5.5,-1) R2(-5,-1.5) R3(-4.5,-1.5) R4(-4,-1.5) R20(4,-1.5) R21(4.5,-1.5) R22(5,-1.5) T1(-5.5,-2) T2(-5,-2) T3(-4.5,-2) T4(-4,-2) T20(4,-2) T21(4.5,-2) T22(5,-2) T23(5.5,-2) U1(-5.5,-2.5) U2(-5,-2.5) U3(-4.5,-2.5) U4(-4,-2.5) U20(4,-2.5) U21(4.5,-2.5) U22(5,-2.5) U23(5.5,-2.5) V2(-5,-3) V3(-4.5,-3) V4(-4,-3) V20(4,-3) V21(4.5,-3) V22(5,-3) W1(-5.5,-3.5) W2(-5,-3.5) W3(-4.5,-3.5) W4(-4,-3.5) W20(4,-3.5) W21(4.5,-3.5) W22(5,-3.5) W23(5.5,-3.5) Y1(-5.5,-4) Y2(-5,-4) Y3(-4.5,-4) Y4(-4,-4) Y5(-3.5,-4) Y6(-3,-4) Y7(-2.5,-4) Y8(-2,-4) Y9(-1.5,-4) Y10(-1,-4) Y11(-0.5,-4) Y12(0,-4) Y13(0.5,-4) Y14(1,-4) Y15(1.5,-4) Y16(2,-4) Y17(2.5,-4) Y18(3,-4) Y19(3.5,-4) Y20(4,-4) Y21(4.5,-4) Y22(5,-4) Y23(5.5,-4)
  silkscreen extent -6.25,-6.07 6.07,6.25, body extent -6.07,-6.07 6.07,6.07, height 1.21
ICC_VFBGA96_9X13_P080 [mm]
  round 0.4 smd mask+0.05: A1(-3.2,6) A2(-2.4,6) A3(-1.6,6) A7(1.6,6) A8(2.4,6) A9(3.2,6) B1(-3.2,5.2) B2(-2.4,5.2) B3(-1.6,5.2) B7(1.6,5.2) B8(2.4,5.2) B9(3.2,5.2) C1(-3.2,4.4) C2(-2.4,4.4) C3(-1.6,4.4) C7(1.6,4.4) C8(2.4,4.4) C9(3.2,4.4) D1(-3.2,3.6) D2(-2.4,3.6) D3(-1.6,3.6) D7(1.6,3.6) D8(2.4,3.6) D9(3.2,3.6) E1(-3.2,2.8) E2(-2.4,2.8) E3(-1.6,2.8) E7(1.6,2.8) E8(2.4,2.8) E9(3.2,2.8) F1(-3.2,2) F2(-2.4,2) F3(-1.6,2) F7(1.6,2) F8(2.4,2) F9(3.2,2) G1(-3.2,1.2) G2(-2.4,1.2) G3(-1.6,1.2) G7(1.6,1.2) G8(2.4,1.2) G9(3.2,1.2) H1(-3.2,0.4) H2(-2.4,0.4) H3(-1.6,0.4) H7(1.6,0.4) H8(2.4,0.4) H9(3.2,0.4) J1(-3.2,-0.4) J2(-2.4,-0.4) J3(-1.6,-0.4) J7(1.6,-0.4) J8(2.4,-0.4) J9(3.2,-0.4) K1(-3.2,-1.2) K2(-2.4,-1.2) K3(-1.6,-1.2) K7(1.6,-1.2) K8(2.4,-1.2) K9(3.2,-1.2) L1(-3.2,-2) L2(-2.4,-2) L3(-1.6,-2) L7(1.6,-2) L8(2.4,-2) L9(3.2,-2) M1(-3.2,-2.8) M2(-2.4,-2.8) M3(-1.6,-2.8) M7(1.6,-2.8) M8(2.4,-2.8) M9(3.2,-2.8) N1(-3.2,-3.6) N2(-2.4,-3.6) N3(-1.6,-3.6) N7(1.6,-3.6) N8(2.4,-3.6) N9(3.2,-3.6) P1(-3.2,-4.4) P2(-2.4,-4.4) P3(-1.6,-4.4) P7(1.6,-4.4) P8(2.4,-4.4) P9(3.2,-4.4) R1(-3.2,-5.2) R2(-2.4,-5.2) R3(-1.6,-5.2) R7(1.6,-5.2) R8(2.4,-5.2) R9(3.2,-5.2) T1(-3.2,-6) T2(-2.4,-6) T3(-1.6,-6) T7(1.6,-6) T8(2.4,-6) T9(3.2,-6)
  silkscreen extent -4.72,-6.55 4.55,6.73, body extent -4.55,-6.55 4.55,6.55, height 1
ICC_WFQFN44-EPAD_5X6_P040 [mm]
  rect 0.8x0.2 smd mask+0.05: 1(-2.45,2.2) 2(-2.45,1.8) 3(-2.45,1.4) 4(-2.45,1) 5(-2.45,0.6) 6(-2.45,0.2) 7(-2.45,-0.2) 8(-2.45,-0.6) 9(-2.45,-1) 10(-2.45,-1.4) 11(-2.45,-1.8) 12(-2.45,-2.2) 23(2.45,-2.2) 24(2.45,-1.8) 25(2.45,-1.4) 26(2.45,-1) 27(2.45,-0.6) 28(2.45,-0.2) 29(2.45,0.2) 30(2.45,0.6) 31(2.45,1) 32(2.45,1.4) 33(2.45,1.8) 34(2.45,2.2)
  rect 0.2x0.8 smd mask+0.05: 13(-1.8,-2.95) 14(-1.4,-2.95) 15(-1,-2.95) 16(-0.6,-2.95) 17(-0.2,-2.95) 18(0.2,-2.95) 19(0.6,-2.95) 20(1,-2.95) 21(1.4,-2.95) 22(1.8,-2.95) 35(1.8,2.95) 36(1.4,2.95) 37(1,2.95) 38(0.6,2.95) 39(0.2,2.95) 40(-0.2,2.95) 41(-0.6,2.95) 42(-1,2.95) 43(-1.4,2.95) 44(-1.8,2.95)
  rect 3.6x4.6 smd paste-1.8 mask+0.05: ep(0,0)
  silkscreen extent -2.5,-3 2.5,3, body extent -2.5,-3 2.5,3, height 0.81
IND_2520_TOKO_DFE252012P [mm]
  rect 0.8x2 smd mask+0.05: 1(-1,0) 2(1,0)
  silkscreen extent -1.35,-1.12 1.35,1.12, body extent -1.35,-1.1 1.35,1.1, height 2
R0402 [mm]
  rect 0.51x0.7 smd mask+0.05: 1(-0.45,0) 2(0.45,0)
  silkscreen extent 0,-0.3 0,0.3, body extent -0.52,-0.3 0.52,0.3, height 0.4
SWI_JIUBABA_C-TS-02H-2-5-B-V-T_R_BLUE [mm] "BLUE"
  rect 0.75x1 smd mask+0.05: 1(-2.225,0.75) 2(2.225,0.75) 3(-2.225,-0.75) 4(2.225,-0.75)
  silkscreen extent -1.85,-1.6 1.85,1.6, body extent -2.45,-1.6 2.45,1.6, height 2.6

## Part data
B1: library part MCD-00172, "Switch HW SMD blue", Manufacturer=JIUBABA, Manufacturer_Part_Number="C-TS-02H-2.5-B-V-T/R BLUE"
C1 C2 C3 C4 C5 C6 C7 C8 C9 C10 C11 C12 C17 C19 C20 C21 C22 C23 C24 C25 C26 C27 C28 C60 C61 C62 C63 C64 C65 C66 C71 C72 C73 C74 C78 C80 C82 C84 C85 C86 C87 C88 C89 C90 C91 C93: library part MCD-00006, "Capacitor, MLCC, 100nF, 16V, X7R, +/-10%, 0402, T=0.5mm", Alternate_Manufacturer=MURATA, Alternate_Manufacturer_Part_Number=GCM155R71C104KA55D, Manufacturer=YAGEO, Manufacturer_Part_Number=CC0402KRX7R7BB104, Package=C0402
C13 C14 C29 C34 C38 C40: library part MCD-00100, "Capacitor, MLCC, 22uF, 6V3, X5R, +/-20%, 0603, T=0,8mm", Manufacturer=MURATA, Manufacturer_Part_Number=GRM188R60J226MEA0J, Package=C0603
C15 C16 C58 C59: library part MCD-01124, "Capacitor, MLCC, 10uF, 10V, X5R, +/-10%, 0603, T=0.8mm", Manufacturer=MURATA, Manufacturer_Part_Number=GRM188R61A106KAAL, Package=C0603
C18 C31 C33 C39 C42 C46: library part MCD-00099, "Capacitor, MLCC, 10uF, 10V, X5R, +/-10%, 0603, T=0,8mm", Manufacturer=MURATA, Manufacturer_Part_Number=GRM188R61A106KE69D, Package=C0603
C30 C32 C35 C36 C37 C41 C45 C47 C48 C50 C53 C54 C55 C70 C75 C76 C77 C92 C94 C95 C96: library part MCD-00095, "Capacitor, MLCC, 1uF, 25V, X5R, +/-10%, 0402, T=0,5mm", Alternate_Manufacturer=MURATA, Alternate_Manufacturer_Part_Number=GRM155R60J105KE19, Manufacturer_Part_Number=GRM155R61E105KA12, Package=C0402
C43 C49 C51 C52: library part MCD-00096, "Capacitor, MLCC, 4.7uF, 6V3, X5R, +/-20%, 0402, T=0,5mm", Manufacturer=MURATA, Manufacturer_Part_Number=GRM155R60J475ME87, Package=C0402
C44 C97: library part MCD-00011, "Capacitor, MLCC, 10nF, 16V, X7R, +/-10%, 0402, T=0.5mm", Manufacturer=YAGEO, Manufacturer_Part_Number=CC0402KRX7R7BB103, Package=C0402
C56 C57: library part MCD-00198, "Capacitor, MLCC, 1nF, 16V, X7R, +/-10%, 0402, T=0.5mm", Manufacturer=YAGEO, Manufacturer_Part_Number=CC0402KRX7R7BB102, Package=C0402
C67 C68 C69: library part MCD-01823, "Capacitor,MLCC, 2.2uF, 6V3, X5R,+/-10%, 0402, T=0.5mm", Manufacturer=MURATA, Manufacturer_Part_Number=GRM155R60J225KE95D, Package=C0402
C79 C81 C83: library part MCD-00012, "Capacitor, MLCC, 2.2uF, 10V, X5R, +/- 10%, 0603, T=0,8mm", Alternate_Manufacturer=KEMET, Alternate_Manufacturer_Part_Number=C0603C225K8PACTU, Manufacturer=YAGEO, Manufacturer_Part_Number=CC0603KRX5R6BB225, Package=C0603
L1 L2 L3 L4: library part MCD-01122, "Power Inductor ,1uH,4.3A max,+/-20%,0.042ohm,2520", Alternate_Manufacturer=N/A, Manufacturer=MURATA, Manufacturer_Part_Number=DFE252012P-1ROM{}P2, Package=2520
R1 R2 R3 R4 R5 R6 R7 R8 R9 R10 R11 R12 R13 R15 R16 R17 R18 R19 R20 R21 R22 R23 R24 R25: library part MCD-00054, "Resistor,56R,0402,1%,1/16W", Manufacturer=YAGEO, Manufacturer_Part_Number=RC0402FR-0756RL, Package=R0402
R14: library part MCD-00067, "Resistor,100R,0402,1%,1/16W", Manufacturer=YAGEO, Manufacturer_Part_Number=RC0402FR-07100RL, Package=R0402
R26 R28 R40: library part MCD-00053, "Resistor,10K,0402,1%,1/16W", Manufacturer=YAGEO, Manufacturer_Part_Number=RC0402FR-0710KL, Package=R0402
R27 R29 R30: library part MCD-00120, "Resistor,240R,0402,1%,1/16W", Manufacturer=YAGEO, Manufacturer_Part_Number=RC0402FR-07240RL, Package=R0402
R31 R32 R33 R34 R35 R36 R42 R44 R45 R46: library part MCD-00061, "Resistor,1K,0402,1%,1/16W", Manufacturer=YAGEO, Manufacturer_Part_Number=RC0402FR-071KL, Package=R0402
R37 R38: library part MCD-00068, "Resistor,1K5,0402,1%,1/16W", Manufacturer=YAGEO, Manufacturer_Part_Number=RC0402FR-071K5L, Package=R0402
R41: library part MCD-00052, "Resistor,0R,0402,5%,1/16W", Manufacturer=YAGEO, Manufacturer_Part_Number=RC0402JR-070RL, Package=R0402
R43: library part MCD-00063, "Resistor,47K,0402,1%,1/16W", Manufacturer=YAGEO, Manufacturer_Part_Number=RC0402FR-0747KL, Package=R0402
U1: library part MCD-00677, "MPU TFBGA12x12 secure boot+crypto", Manufacturer=STMICROELECTRONICS
U2 U6: library part MCD-01811, "Memory,DDR3L,4Gb,256Mbx16,933Mhz,1V35,TFBGA", Manufacturer=NANYA
U4: library part MCD-00303, "STM PMIC WFQFN 5.0x6.0x0.80 44L 0.4 pitch", Manufacturer=STMICROELECTRONICS, Manufacturer_Part_Number=STPMU1APQR
U5: library part MCD-00110, "Memory,e-MMC,4GB,3V3,WFBGA,153pins", Manufacturer=TOSHIBA, Manufacturer_Part_Number=THGBMDG5D1LBAIL

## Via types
v1: diameter 0.4, hole 0.2, Top Layer to Bottom Layer, tented both sides, 302 vias
v2: diameter 0.6, hole 0.3, Top Layer to Bottom Layer, tented both sides, 80 vias
v3: diameter 0.25, hole 0.1, Top Layer to Signal Layer 1, tented top, 70 vias
v4: diameter 0.25, hole 0.1, Top Layer to Signal Layer 1, tented both sides, 6 vias
v5: diameter 0.25, hole 0.1, Top Layer to Bottom Layer, tented top, 2 vias

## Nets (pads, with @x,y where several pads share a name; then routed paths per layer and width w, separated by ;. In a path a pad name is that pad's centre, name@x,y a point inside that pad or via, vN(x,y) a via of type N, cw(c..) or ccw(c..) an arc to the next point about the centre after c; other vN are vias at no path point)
3V3: C32.2 C40.2 C78.2 C79.2 L4.2 U4.22 U4.27 U5.E6 U5.F5 U5.J10 U5.K9 | length 51.3
  Top Layer w0.1: v3(12.25,81.45) U4.27@12.25,82.025
  Top Layer w0.175: U5.J10@27.7,88.475 U5.K9@28.2,88.975 v1(28.2,89.45) ; U5.E6@29.7,86.475 U5.F5@30.2,86.975 v1(30.625,86.975)
  Top Layer w0.2: 9.725,82.5 U4.22@9.9,82.675 9.9,82.491
  Top Layer w0.3: 9.625,82.5 9.725,82.5
  Top Layer w0.4: C32.2@7.7,80.075 7.9,80.075 8.187,80.362 8.635,80.81 8.635,81.41 9.725,82.5
  Signal Layer 1 w0.2: v2(11.575,74.9) 12.25,75.575 v3(12.25,81.45)
  Signal Layer 2 w0.3: v2(8.3,80.25) 7.075,79.025 7.075,76.475 8.65,74.9 v2(10.2,74.9) v2(10.9,74.9) v2(11.575,74.9)
  Bottom Layer w0.1: C79.2@27.35,89.575 C79.2@27.475,89.45
  Bottom Layer w0.13: C78.2@30.025,86.9 C78.2@30.125,87 ; v1@30.6,87 v1(30.625,86.975)
  Bottom Layer w0.3: v2(11.575,74.9) 17.275,80.6 17.275,82.625 18.775,84.125 22.575,84.125 25.25,86.8 25.25,87.475 C79.2@27.35,89.575 ; C79.2@27.475,89.45 28.175,89.45 28.188,89.437 29.325,88.3 29.325,87.6 C78.2@30.025,86.9 ; C78.2@30.125,87 v1@30.6,87
5V_VIN: C18.2 C31.2 C33.2 C39.2 C41.2 C51.2 R43.2 U4.8 U4.12 U4.19 U4.24 U4.28 U4.36 U4.37 | length 23.6
  Top Layer w0.2: 8.775,83.875 U4.19@9.9,83.875 ; 11.05,81.3 U4.24@11.05,82.025 ; U4.8@12.25,86.925 12.25,88.76 ; U4.28@12.65,82.025 12.65,80.975 13.625,80 C31.2@13.625,79.25 ; U4.36@15.8,83.075 16.45,83.075 C51.2@16.7,82.825 ; U4.37@15.8,83.475 16.825,83.475
  Top Layer w0.3: C41.2@7.7,83.325 8.25,83.875 8.775,83.875 ; v1(8.075,78.775) v1(8.55,78.775) v1(9,78.775) ; v2(18.575,81.45) 19.325,81.45 R43.2@19.461,81.586
  Top Layer w0.4: v2(4.725,83.15) v2(5.35,83.15) 5.735,82.765 7.335,82.765 7.7,83.13 C41.2@7.7,83.325
  Top Layer w0.45: 16.625,83.55 18.078,83.55 18.503,83.125 v2(18.575,83.125) ; C51.2@16.7,82.825 16.7,82.127 17.377,81.45 v2(18.575,81.45)
  Signal Layer 2 w0: 7.051,81.828 9.199,83.975
  other v1: 13.225,78.725 13.725,78.725 14.2,78.725
  other v2: 6.075,88.575 6.075,89.2 6.075,89.825 11.85,89.9 12.55,89.9 7.278,93.4
DDR_A0: R1.1 U1.L20 U2.N3 U6.N3 | length 75.8
  Top Layer w0.12: v1(35.625,63.5) 35.7,63.5 U1.L20@36,63.2 ; U2.N3@53.925,60.3 v1(54.325,60.7) ; U6.N3@73.75,64.525 v1(74.15,64.925)
  Bottom Layer w0.12: v1(35.625,63.5) 41.35,63.5 41.565,63.715 41.951,63.715 42.066,63.6 42.225,63.6 42.475,63.85 42.475,65.95 41.6,66.825 41.6,73.275 42.1,73.775 48,73.775 48.5,73.275 48.5,61.375 49.85,60.025 53.8,60.025 54.325,60.55 v1(54.325,60.7) 54.325,60.95 54.685,61.31 54.685,61.585 55.475,62.375 57.125,62.375 57.65,61.85 63.775,61.85 66.175,64.25 73.625,64.25 74.15,64.775 v1(74.15,64.925) 74.15,65.2 74.575,65.625 74.575,65.9 74.875,66.2 75,66.2 75.605,66.805 77.505,66.805 78.4,67.7 80.2,67.7 81.05,68.55 R1.1@81.075,68.55 R1.1@81.25,68.55
DDR_A1: R2.1 U1.P22 U2.P7 U6.P7 | length 77.9
  Top Layer w0.09: U1.P22@37,61.7 37.24,61.46 37.895,61.46 37.975,61.38 38.47,61.38 38.605,61.245 39.218,61.245 39.253,61.21 39.515,61.21 39.9,60.825 v1(40.175,60.825)
  Top Layer w0.12: U2.P7@53.125,57.1 v1(53.525,56.7) ; U6.P7@72.95,61.325 v1(73.35,60.925)
  Bottom Layer w0.12: v1(40.175,60.825) 40.175,54.7 40.5,54.375 40.5,52 40.75,51.75 41.65,51.75 41.9,52 41.9,55.4 42.075,55.575 44.75,55.575 44.85,55.675 44.85,55.875 44.75,55.975 43.65,55.975 43.525,56.1 43.525,56.225 43.65,56.35 45.125,56.35 45.3,56.175 45.3,51.125 45.625,50.8 46.625,50.8 46.875,51.05 46.875,56.075 47.075,56.275 48.95,56.275 49.825,57.15 53.075,57.15 v1(53.525,56.7) 53.816,56.7 54.176,56.34 54.54,56.34 54.975,56.775 55.525,56.775 56.25,56.05 59.1,56.05 60.025,56.975 65.125,56.975 67.775,59.625 67.775,59.85 69.3,61.375 72.9,61.375 v1(73.35,60.925) 73.641,60.925 74.001,60.565 74.365,60.565 74.8,61 75.35,61 76.075,60.275 79.775,60.275 80.25,59.8 80.25,58.05 80.5,57.8 R2.1@80.5,57.2
DDR_A2: R3.1 U1.J20 U2.P3 U6.P3 | length 73.7
  Top Layer w0.12: v1(35.625,64.025) 35.8,64.2 U1.J20@36,64.2 ; U2.P3@53.125,60.3 v1(53.525,60.7) ; U6.P3@72.95,64.525 v1(73.35,64.925)
  Bottom Layer w0.12: v1(35.625,64.025) 40.025,64.025 40.125,64.125 40.125,64.775 39.975,64.925 39.525,64.925 39.3,65.15 39.3,66.475 39.55,66.725 40.2,66.725 40.775,67.3 40.775,73.925 41.725,74.875 48.175,74.875 49.25,73.8 49.25,61.575 50.25,60.575 53.425,60.575 53.525,60.675 v1(53.525,60.7) 53.525,60.991 53.925,61.391 53.925,61.65 54.135,61.86 54.219,61.86 57.484,65.125 64.475,65.125 64.8,64.8 73.25,64.8 73.35,64.9 v1(73.35,64.925) 73.35,65.216 73.71,65.576 73.71,65.81 74.595,66.695 74.699,66.695 75.319,67.315 77.09,67.315 78.19,68.415 79.015,68.415 79.125,68.525 R3.1@79.125,68.55 R3.1@79.25,68.55
DDR_A3: R4.1 U1.K22 U2.N2 U6.N2 | length 74.7
  Top Layer w0.09: U1.K22@37,63.7 37.24,63.46 39.265,63.46 39.325,63.4 39.656,63.4 39.691,63.435 40.259,63.435 40.294,63.4 41.275,63.4 41.95,64.075 v1(42.075,64.075)
  Top Layer w0.12: U2.N2@53.925,61.1 v1(54.325,61.5) ; U6.N2@73.75,65.325 v1(74.15,65.725)
  Bottom Layer w0.12: v1(42.075,64.075) 42.075,64.925 41.9,65.1 40.925,65.1 40.675,65.35 40.675,65.675 41.15,66.15 41.15,73.65 41.95,74.45 48,74.45 48.875,73.575 48.875,61.475 50.05,60.3 53.675,60.3 53.925,60.55 53.925,61.08 v1@54.335,61.49 ; v1(54.325,61.5) 54.325,61.6 55.575,62.85 57.075,62.85 57.775,62.15 63.5,62.15 65.875,64.525 73.5,64.525 73.75,64.775 73.75,65.305 v1@74.16,65.715 ; v1(74.15,65.725) 74.15,65.825 74.78,66.455 74.88,66.455 75.5,67.075 77.275,67.075 78.225,68.025 79.475,68.025 80,68.55 R4.1@80.1,68.55 R4.1@80.25,68.55
DDR_A4: R5.1 U1.V20 U2.P8 U6.P8 | length 69.7
  Top Layer w0.12: v1(35.6,59.9) 35.634,59.9 35.834,59.7 U1.V20@36,59.7 ; v1(52.7,54.875) 52.725,54.9 52.725,55.9 U2.P8@53.125,56.3 ; v1@72.54,59.175 72.54,60.115 U6.P8@72.95,60.525
  Bottom Layer w0.12: v1(35.6,59.9) 35.634,59.9 36.434,59.1 36.434,57.291 36.6,57.125 36.875,57.125 37.625,56.375 37.625,52.775 38.175,52.225 38.175,48.4 39.2,47.375 48.05,47.375 48.15,47.475 48.15,47.7 48.075,47.775 45.35,47.775 45.275,47.85 45.275,48.1 45.35,48.175 49.275,48.175 49.65,48.55 49.65,54.3 50.75,55.4 52.125,55.4 52.955,54.57 55.605,54.57 55.925,54.25 56.55,54.25 56.625,54.325 62.1,54.325 62.325,54.55 65.925,54.55 69.9,58.525 69.9,58.925 70.6,59.625 71.4,59.625 71.56,59.785 71.94,59.785 v1(72.55,59.175) 72.875,58.85 73.05,58.85 73.75,58.15 R5.1@73.75,57.2 ; v1@52.65,54.875 v1@52.675,54.875
DDR_A5: R6.1 U1.H20 U2.P2 U6.P2 | length 69.4
  Top Layer w0.12: v1(35.125,64.175) 35.65,64.7 U1.H20@36,64.7 ; U2.P2@53.125,61.1 v1(53.525,61.5) ; U6.P2@72.95,65.325 v1(73.35,65.725)
  Bottom Layer w0.12: v1(35.125,64.175) 35.425,64.475 38.45,64.475 38.8,64.825 38.8,66.775 39.15,67.125 39.875,67.125 40.375,67.625 40.375,74.15 41.525,75.3 48.375,75.3 49.6,74.075 49.6,61.7 50.45,60.85 52.875,60.85 v1(53.525,61.5) 53.525,61.85 53.915,62.24 53.915,62.615 54.225,62.925 54.875,62.925 57.425,65.475 64.6,65.475 65,65.075 72.5,65.075 72.841,65.416 73.041,65.416 v1(73.35,65.725) 73.35,66.075 73.6,66.325 73.875,66.325 74.125,66.575 74.125,67.3 74.25,67.425 R6.1@74.25,68.55
DDR_A6: R7.1 U1.W20 U2.R8 U6.R8 | length 68.9
  Top Layer w0.12: v1(35.625,59.4) 35.825,59.2 U1.W20@36,59.2 ; v1(51.9,55.025) 51.9,56.15 52.05,56.3 U2.R8@52.325,56.3 ; v1(71.75,59.425) 71.76,59.435 71.76,60.135 U6.R8@72.15,60.525
  Bottom Layer w0.12: v1(35.625,59.4) 36,59.025 36,56.85 36.225,56.625 36.675,56.625 37.125,56.175 37.125,52.65 37.75,52.025 37.75,48.2 39,46.95 51.15,46.95 51.225,47.025 51.225,47.3 51.15,47.375 48.65,47.375 48.575,47.45 48.575,47.675 48.65,47.75 50.075,47.75 50.15,47.825 50.15,54.273 50.902,55.025 v1(51.9,55.025) 52.595,54.33 55.454,54.33 56.194,53.59 65.54,53.59 70.225,58.275 70.225,58.825 70.785,59.385 71.79,59.385 72.575,58.6 72.575,57.375 R7.1@72.75,57.2
DDR_A7: R8.1 U1.E20 U2.R2 U6.R2 | length 68
  Top Layer w0.12: v1(35.625,66) 35.825,66.2 U1.E20@36,66.2 ; v1@51.925,62.419 51.925,61.5 U2.R2@52.325,61.1 ; v1(71.75,66.525) 71.75,65.725 U6.R2@72.15,65.325
  Bottom Layer w0.12: v1(35.625,66) 37.2,66 37.55,66.35 37.55,67.775 38,68.225 38.725,68.225 39.075,68.575 39.075,75.825 39.825,76.575 49.225,76.575 50.725,75.075 50.725,62.175 50.9,62 51.465,62 v1(51.905,62.44) 51.905,64.455 52.45,65 54.925,65 56.475,66.55 64.95,66.55 65.275,66.225 71.45,66.225 v1(71.75,66.525) 71.75,67.5 71.25,68 R8.1@71.25,68.55
DDR_A8: R9.1 U1.Y20 U2.T8 U6.T8 | length 68.2
  Top Layer w0.09: v1(35.25,59.05) 35.65,59.05 U1.Y20@36,58.7
  Top Layer w0.12: v1@51.185,54.625 51.185,55.684 51.525,56.024 U2.T8@51.525,56.3 ; v1@70.99,59.025 70.99,59.885 71.35,60.245 U6.T8@71.35,60.525
  Bottom Layer w0.12: v1(35.25,59.05) 35.55,58.75 35.55,56.725 36.65,55.625 36.65,52.5 37.35,51.8 37.35,47.975 38.8,46.525 51.4,46.525 51.675,46.8 51.675,49.1 51.575,49.2 51.325,49.2 51.2,49.075 51.2,47.975 51.1,47.875 50.725,47.875 50.625,47.975 50.625,54.175 51.075,54.625 v1(51.175,54.625) 51.7,54.625 52.875,53.45 55.725,53.45 55.956,53.219 65.744,53.219 70.525,58 70.525,58.525 v1(71.025,59.025) 71.6,58.45 71.6,57.35 R9.1@71.75,57.2
DDR_A9: R10.1 U1.G20 U2.R3 U6.R3 | length 71.2
  Top Layer w0.12: v1(35.575,65.3) 35.9,65.3 U1.G20@36,65.2 ; U2.R3@52.325,60.3 52.725,60.7 v1(52.725,61.5) ; U6.R3@72.15,64.525 72.55,64.925 v1(72.55,65.725)
  Bottom Layer w0.12: v1(35.575,65.3) 36.2,65.3 36.325,65.175 36.325,64.9 36.4,64.825 36.9,64.825 37,64.925 37,65.225 37.1,65.325 37.6,65.325 37.725,65.2 37.725,64.975 37.825,64.875 38.25,64.875 38.4,65.025 38.4,67.35 38.55,67.5 39.625,67.5 39.925,67.8 39.925,75.075 40.575,75.725 48.675,75.725 49.975,74.425 49.975,61.825 50.65,61.15 52.375,61.15 v1(52.725,61.5) 53.6,62.375 53.6,62.75 54.125,63.275 54.8,63.275 54.925,63.4 54.925,64.075 55.075,64.225 55.725,64.225 55.975,64.475 55.975,65.125 56.675,65.825 64.725,65.825 65.175,65.375 72.2,65.375 v1(72.55,65.725) 73.375,66.55 73.375,67.175 73.25,67.3 R10.1@73.25,68.55
DDR_A10: R11.1 U1.R22 U2.L7 U6.L7 | length 75.6
  Top Layer w0.09: U1.R22@37,61.2 37.169,61.2 37.249,61.28 37.8,61.28 37.87,61.21 38.34,61.21 38.625,60.925 39.05,60.925 v1(39.075,60.9)
  Top Layer w0.12: v1(55.125,55.9) 55.125,56.7 U2.L7@55.525,57.1 ; v1(74.95,60.125) 74.95,60.925 U6.L7@75.35,61.325
  Bottom Layer w0.12: v1@39.075,60.925 v1(39.075,60.9) 39.075,57.9 39.775,57.2 39.775,54.425 40.125,54.075 40.125,51.6 40.4,51.325 42.025,51.325 42.325,51.625 42.325,54.125 42.55,54.35 43.7,54.35 43.8,54.45 43.8,54.65 43.7,54.75 42.9,54.75 42.8,54.85 42.8,55.05 42.9,55.15 44.1,55.15 44.875,54.375 44.875,50.925 45.45,50.35 46.85,50.35 47.325,50.825 47.325,55.6 47.55,55.825 48.9,55.825 49.975,56.9 52.65,56.9 53.21,56.34 53.835,56.34 54.055,56.12 54.905,56.12 v1(55.125,55.9) 55.95,55.9 56.05,55.8 59.25,55.8 59.825,56.375 61.9,56.375 62.075,56.2 64.875,56.2 68.175,59.5 68.175,59.7 69.6,61.125 72.475,61.125 73.035,60.565 73.66,60.565 73.9,60.325 74.75,60.325 v1(74.95,60.125) 75.775,60.125 75.875,60.025 79.475,60.025 79.95,59.55 79.95,58.025 79.575,57.65 79.575,57.275 R11.1@79.512,57.213
DDR_A11: R12.1 U1.R20 U2.R7 U6.R7 | length 77
  Top Layer w0.09: v1(35.575,61.725) 35.636,61.725 36,61.361 U1.R20@36,61.2
  Top Layer w0.12: v1@51.015,56.42 v1@51.015,56.424 ; v1(51.015,56.49) 51.245,56.72 51.654,56.72 52.034,57.1 U2.R7@52.325,57.1 ; v1(70.85,60.765) 71.03,60.945 71.77,60.945 U6.R7@72.15,61.325
  Bottom Layer w0.12: v1(35.575,61.725) 38.475,61.725 38.6,61.6 38.6,61.325 38.5,61.225 37.325,61.225 37.225,61.125 37.225,60.775 37.4,60.6 38.525,60.6 38.65,60.475 38.65,60.2 38.55,60.1 38.075,60.1 37.9,59.925 37.9,59.65 38.075,59.475 38.375,59.475 38.5,59.35 38.5,57.9 39.35,57.05 39.35,54.275 39.775,53.85 39.775,51.325 40.225,50.875 42.2,50.875 42.75,51.425 42.75,53.7 42.95,53.9 44.2,53.9 44.45,53.65 44.45,50.75 45.275,49.925 47.075,49.925 47.8,50.65 47.8,55.125 48.025,55.35 48.85,55.35 50.15,56.65 50.55,56.65 50.71,56.49 v1(51.015,56.49) 52.635,56.49 53.068,56.057 53.743,56.057 53.9,55.9 54.55,55.9 54.925,55.525 61.1,55.525 61.175,55.6 61.175,55.85 61.35,56.025 61.7,56.025 61.85,55.875 65.075,55.875 68.5,59.3 68.5,59.5 69.835,60.835 v1@70.85,60.835 ; v1@70.89,60.795 72.38,60.795 72.892,60.283 73.567,60.283 73.775,60.075 74.433,60.075 74.758,59.75 77.75,59.75 78.275,59.225 78.275,58.025 78.5,57.8 R12.1@78.5,57.2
